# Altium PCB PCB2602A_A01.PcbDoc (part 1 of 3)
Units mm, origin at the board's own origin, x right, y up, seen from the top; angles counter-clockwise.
Board outline 30.4 x 45.4 mm, 8 copper layers (Top Layer, Signal Layer 2, Signal Layer 3, Signal Layer 4, Signal Layer 5, Signal Layer 6, Signal Layer 7, Bottom Layer), stack 1.594 mm thick; 180 components, 124 nets, 679 pads, 487 vias.
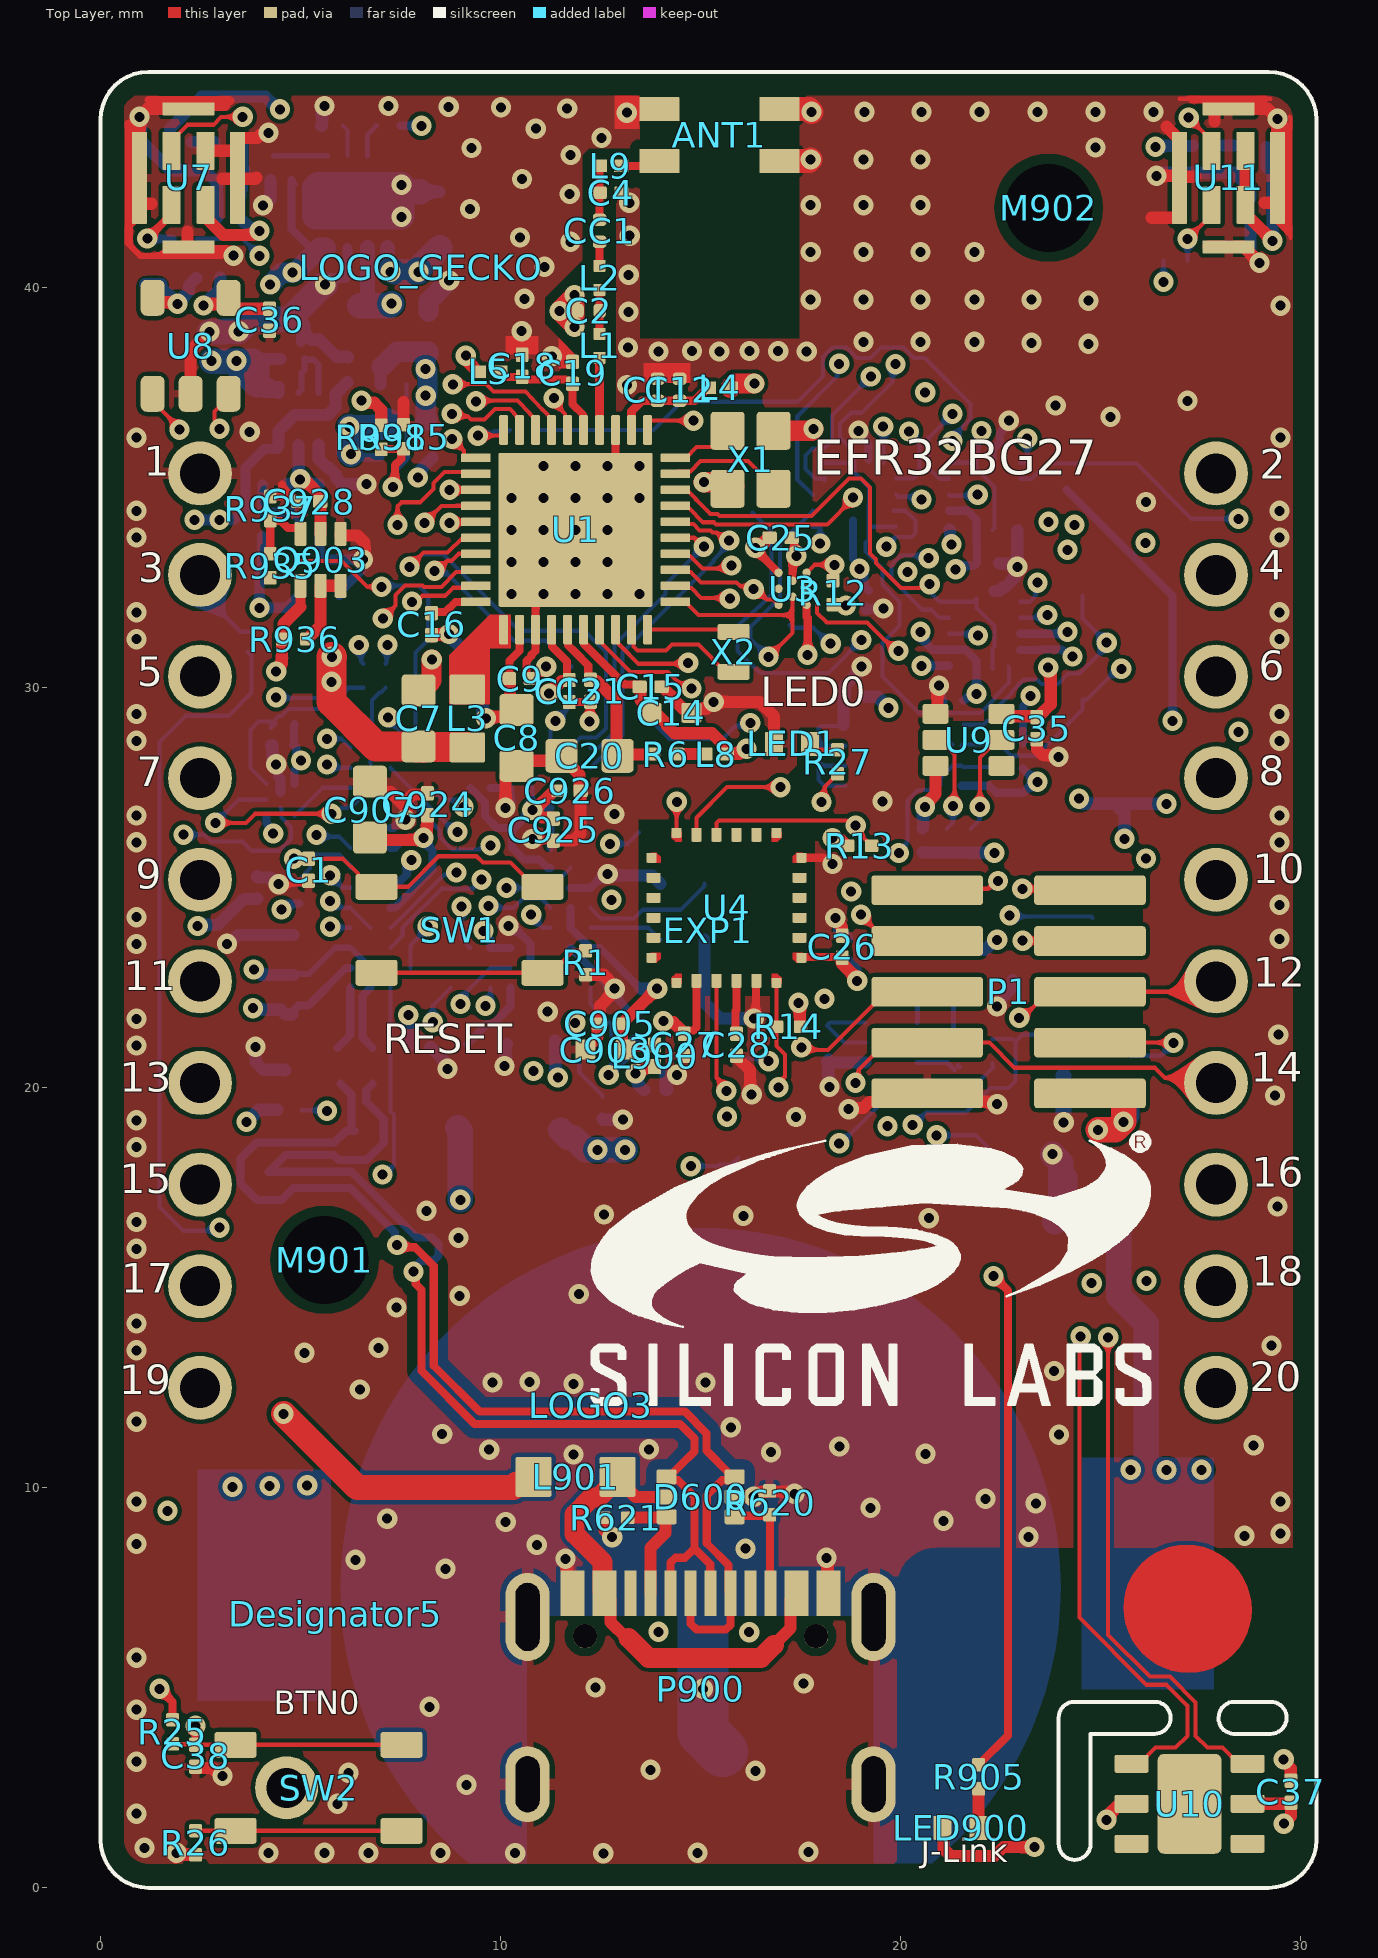
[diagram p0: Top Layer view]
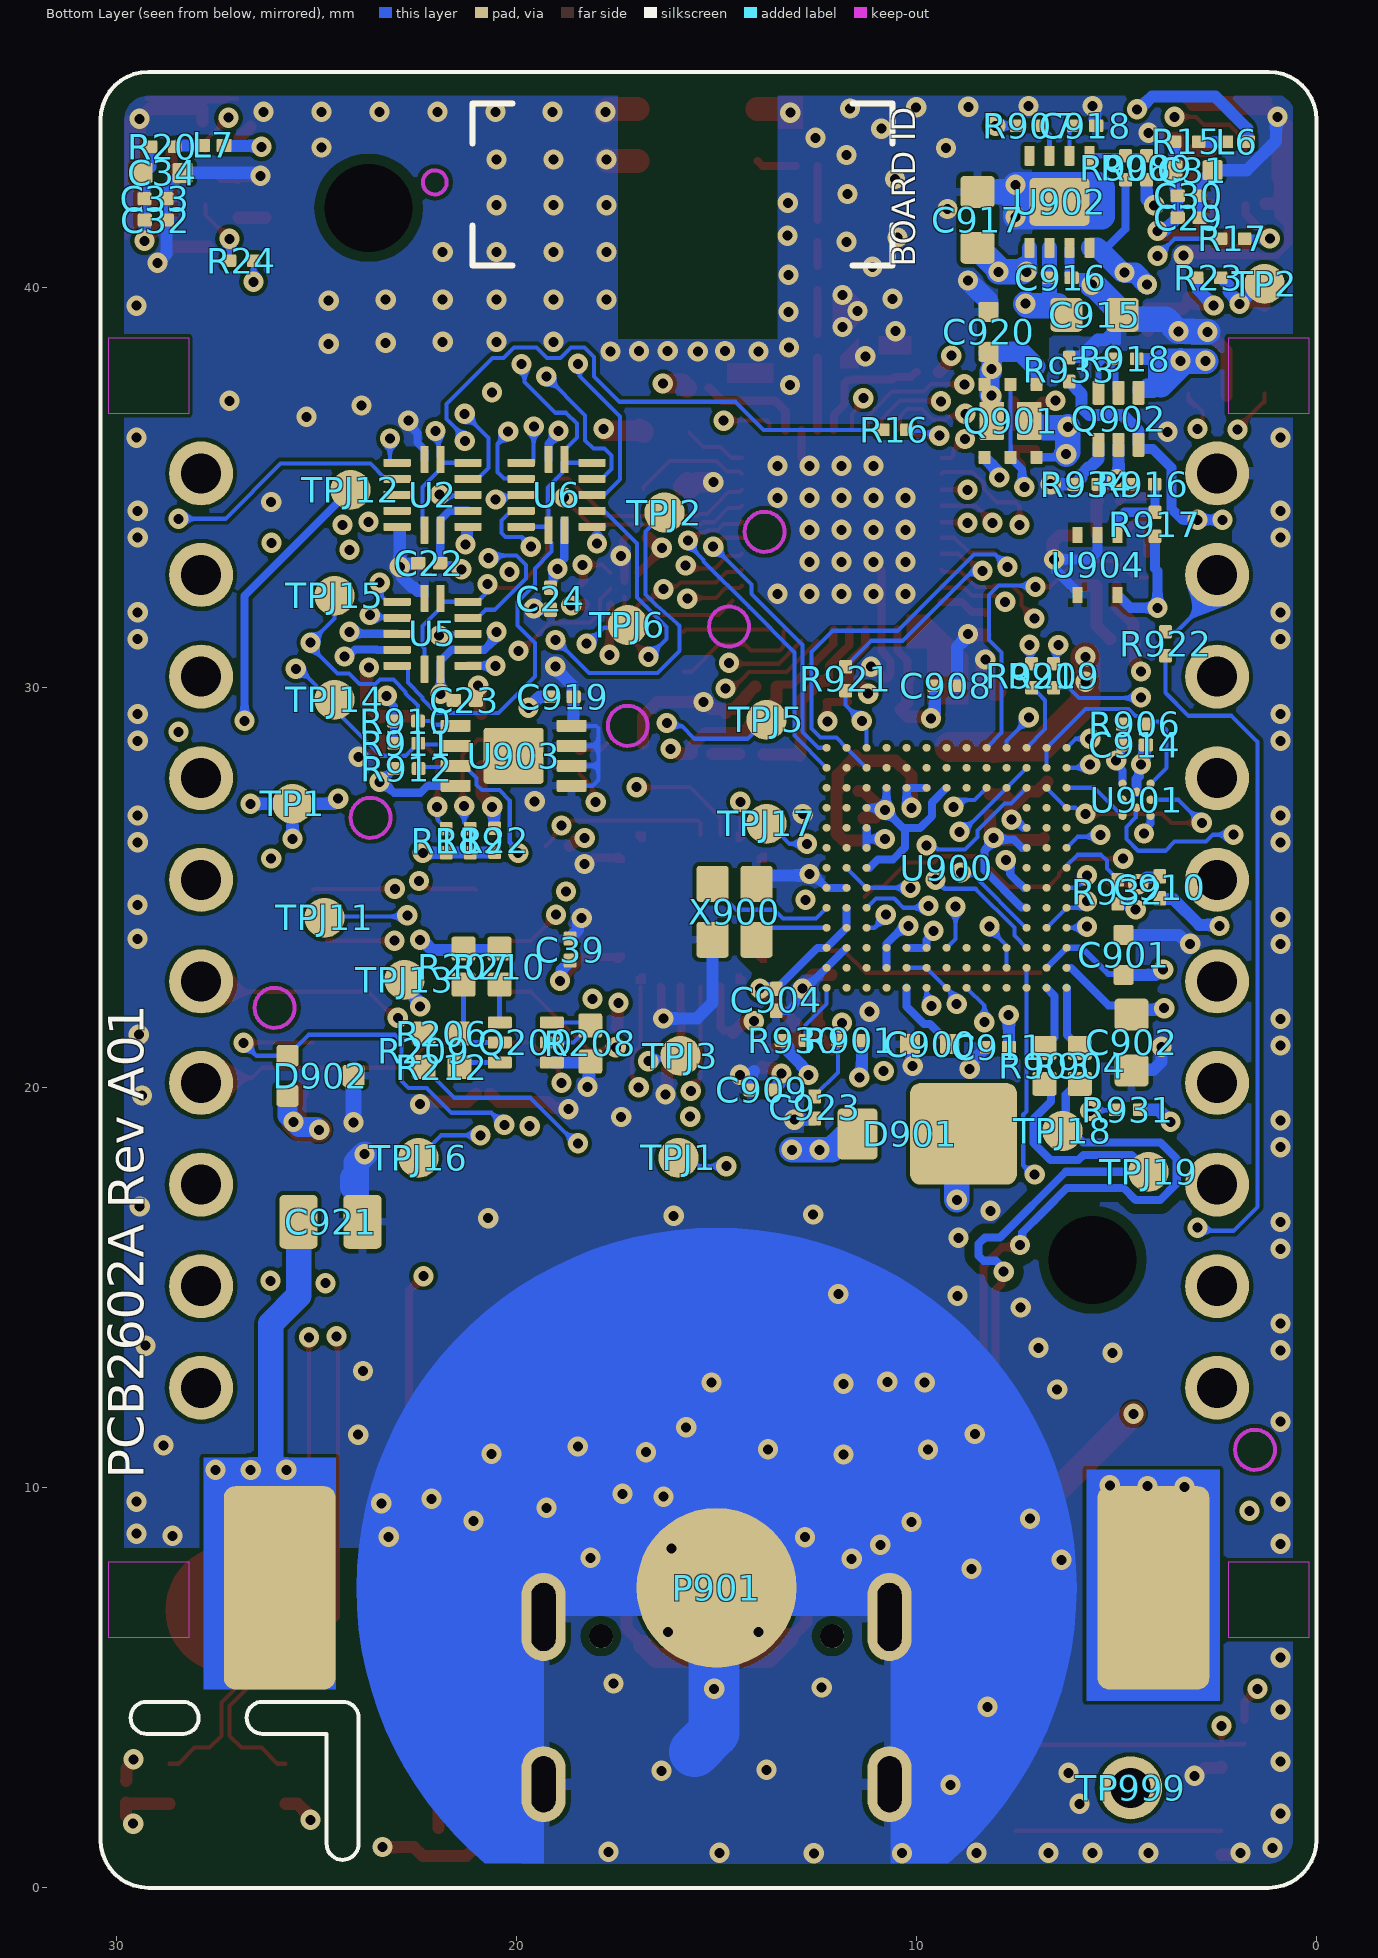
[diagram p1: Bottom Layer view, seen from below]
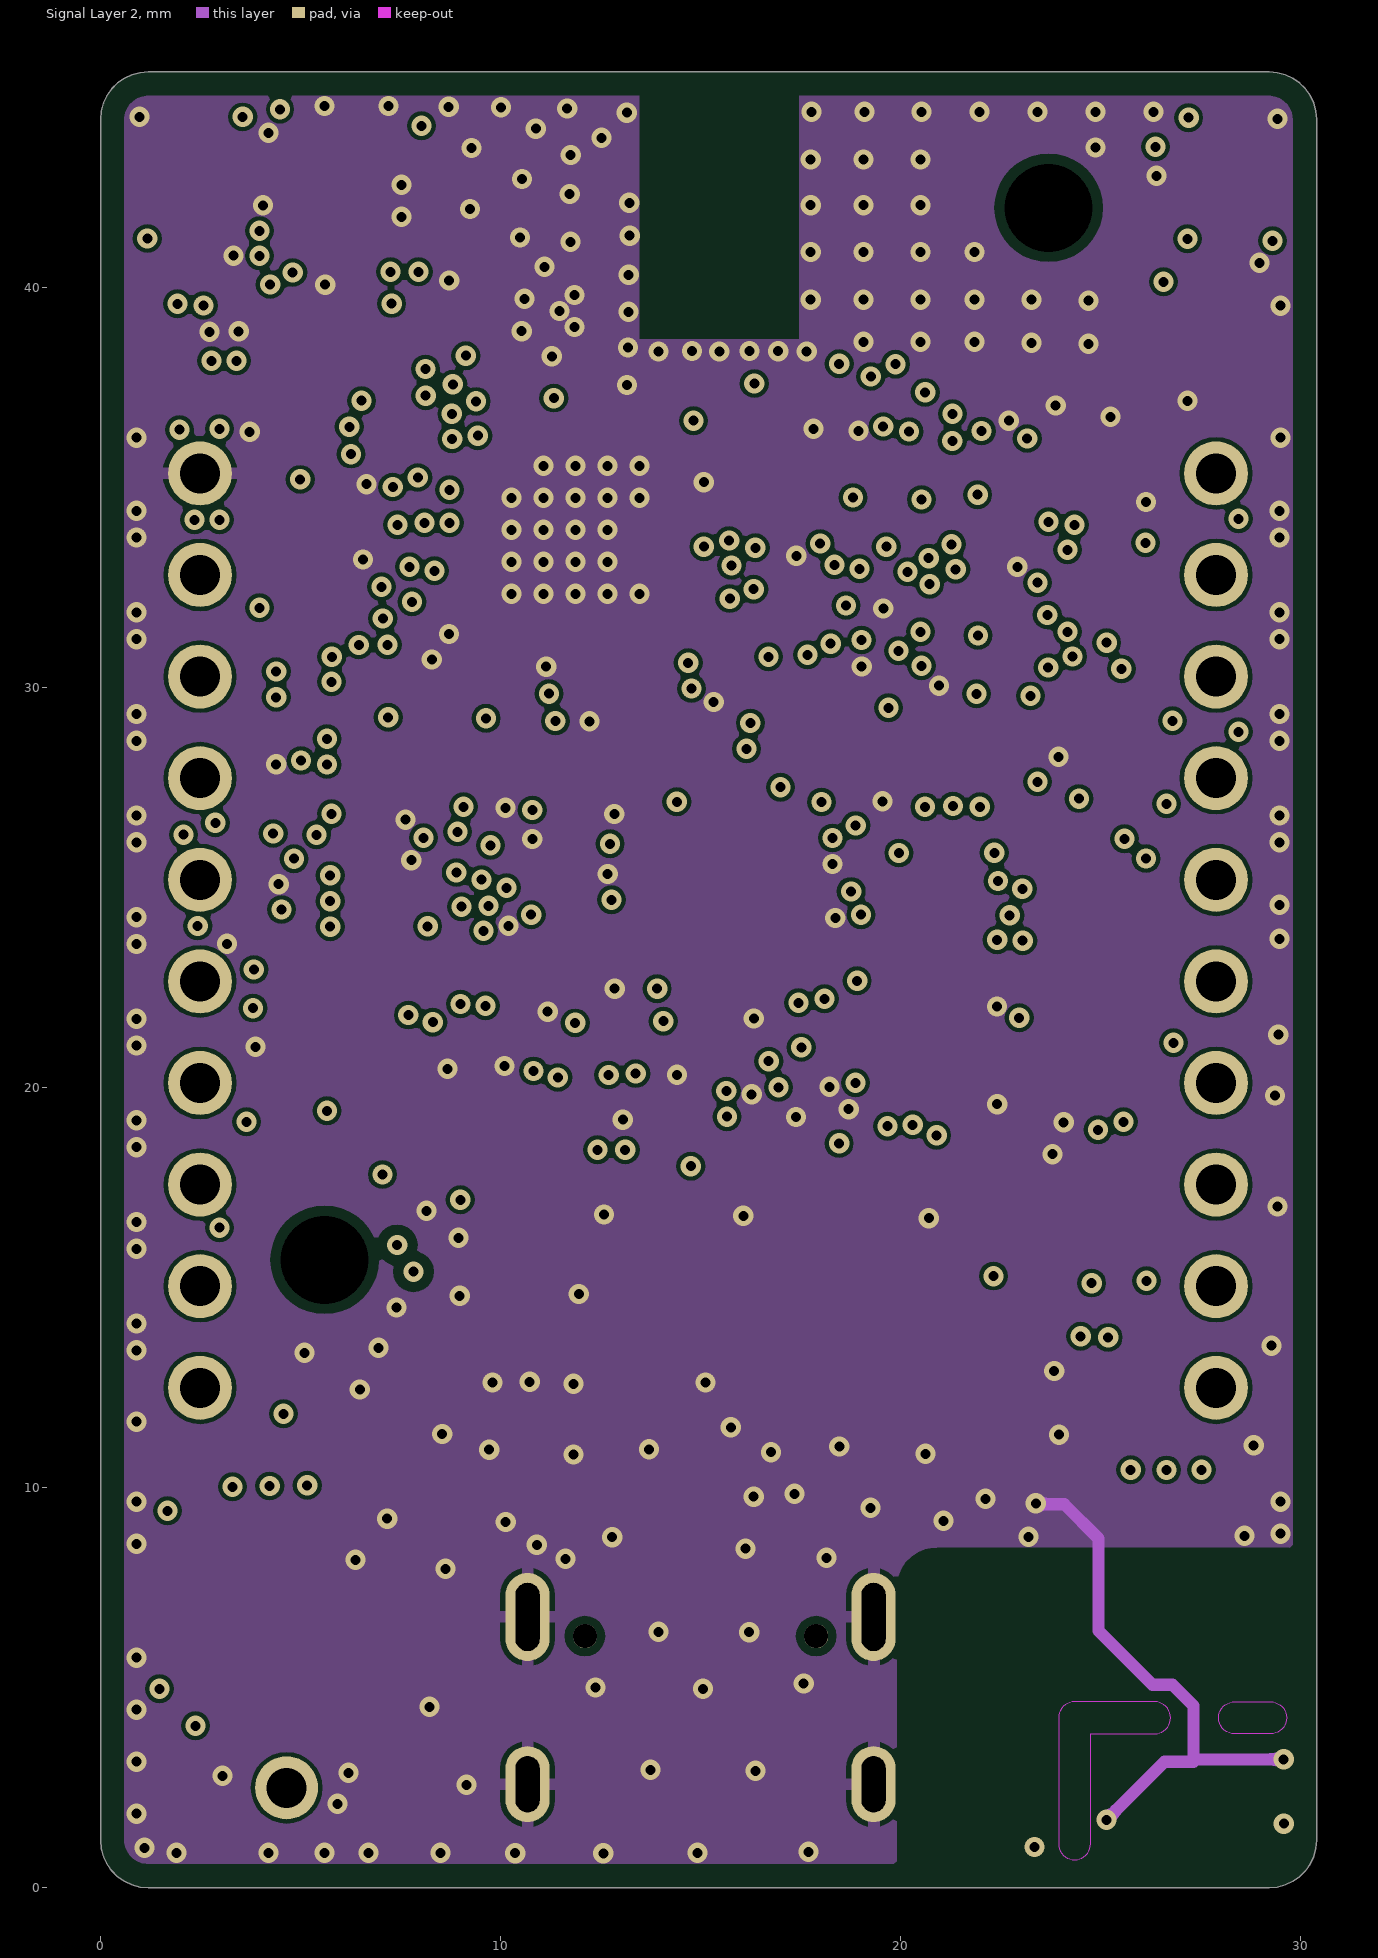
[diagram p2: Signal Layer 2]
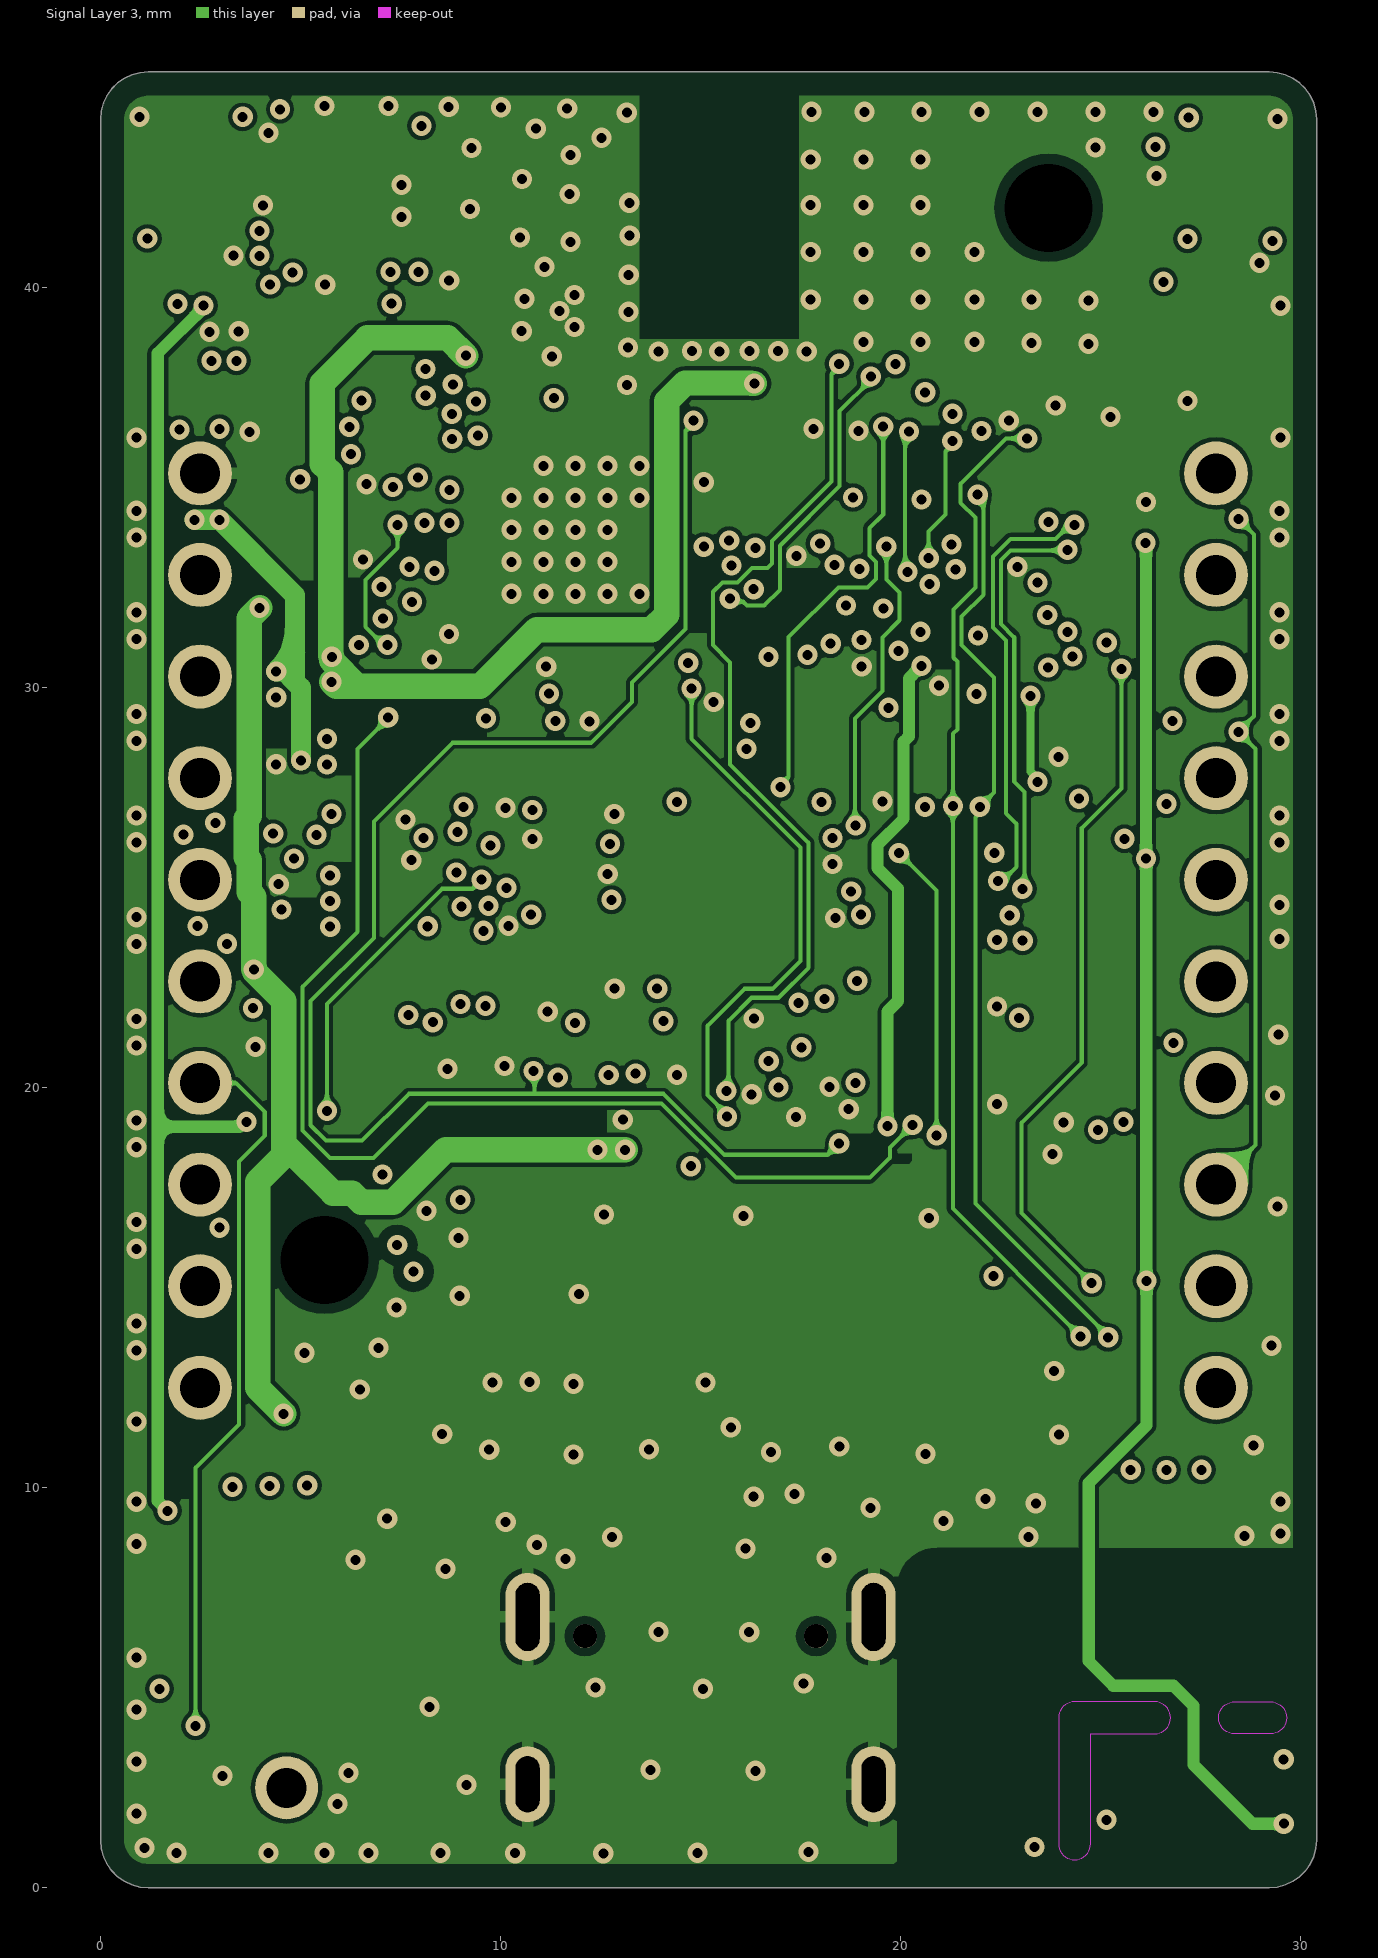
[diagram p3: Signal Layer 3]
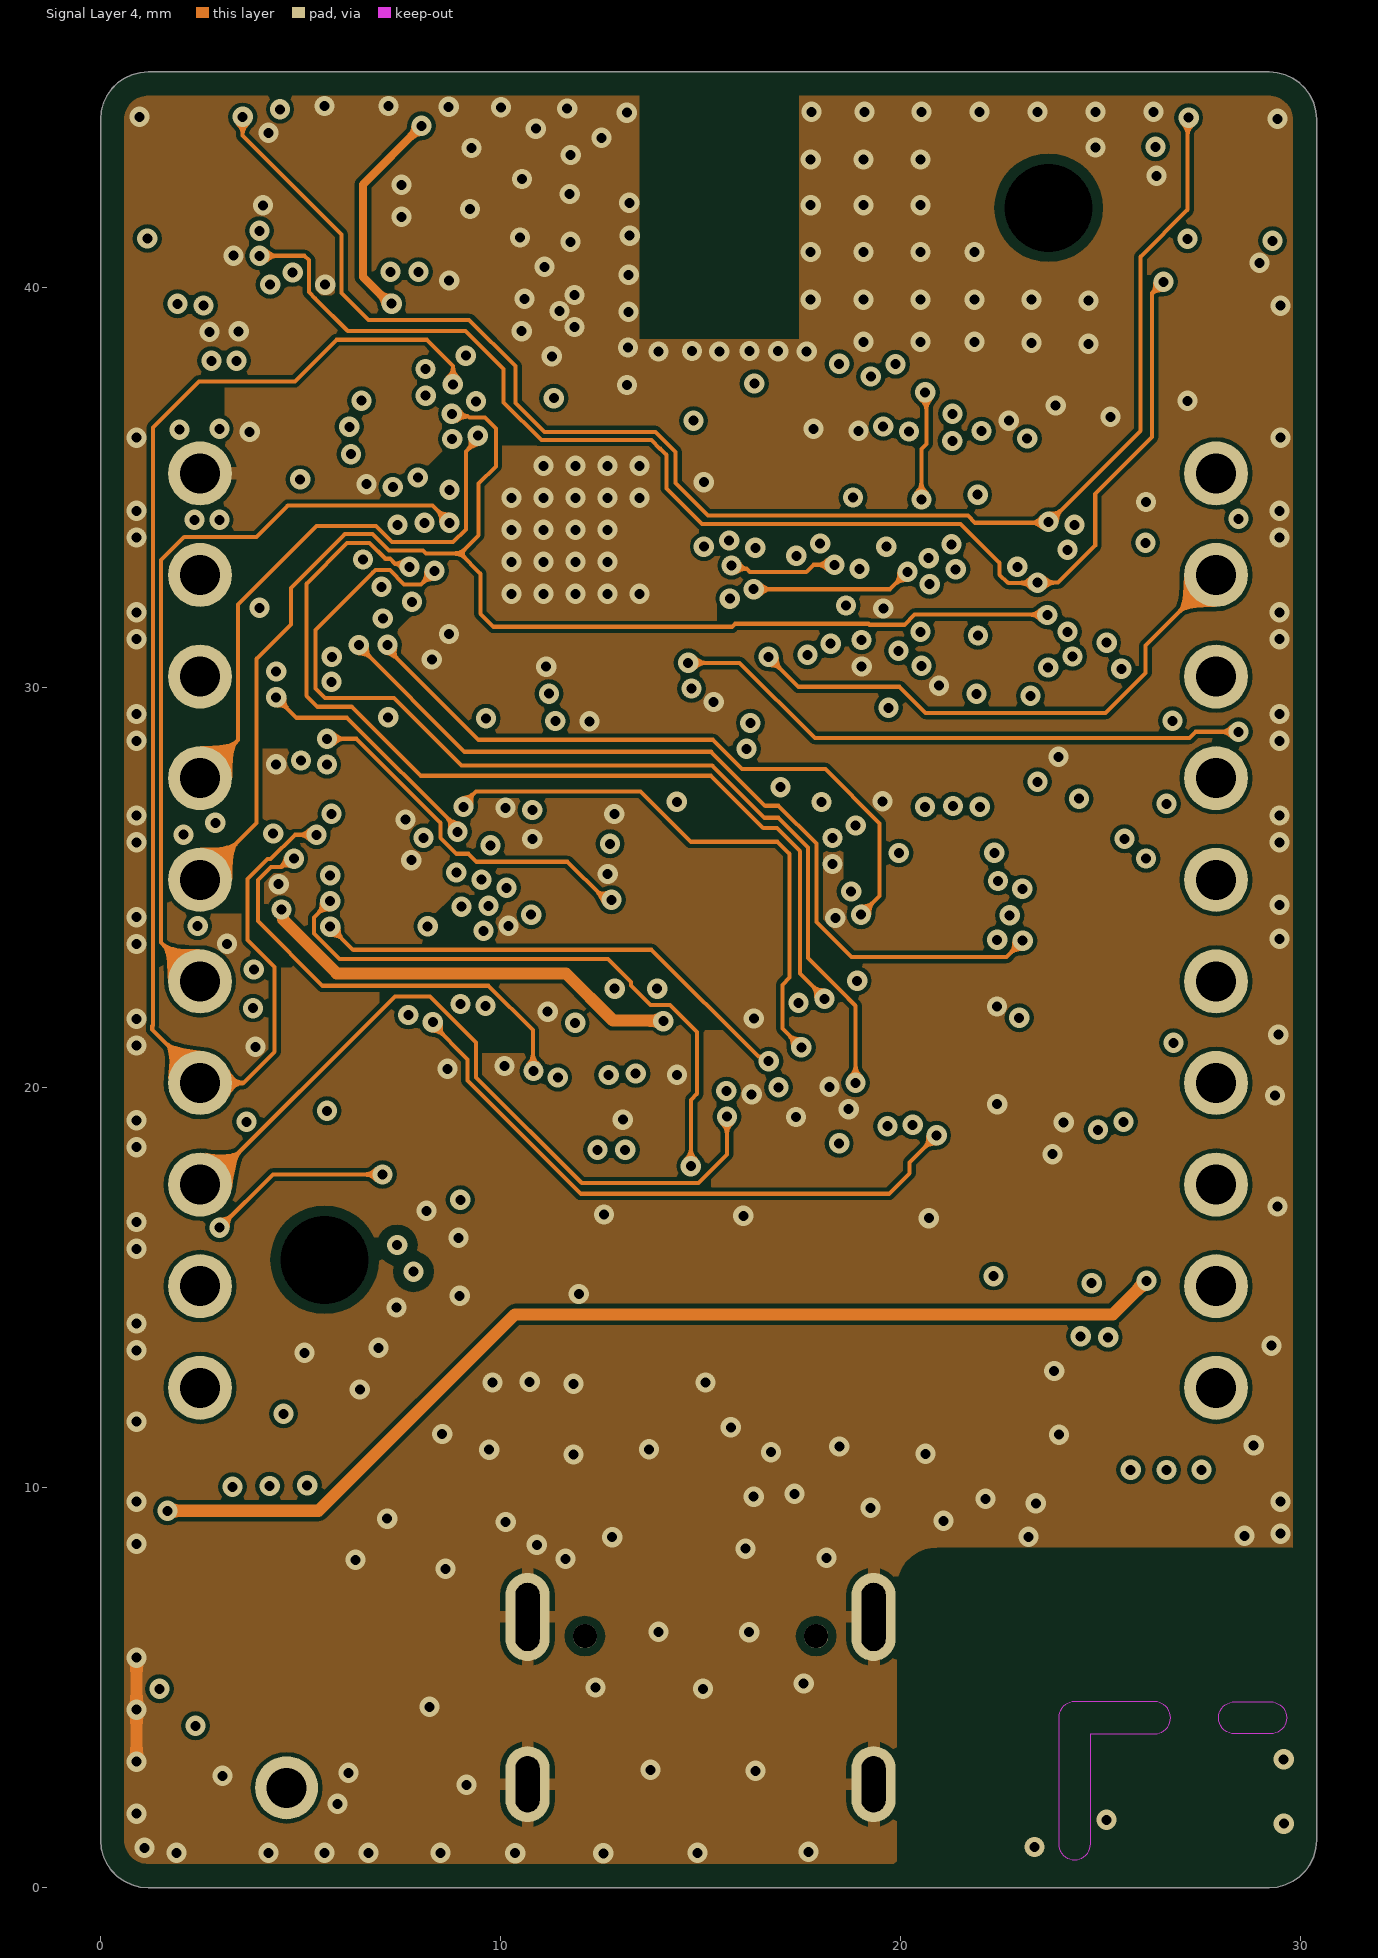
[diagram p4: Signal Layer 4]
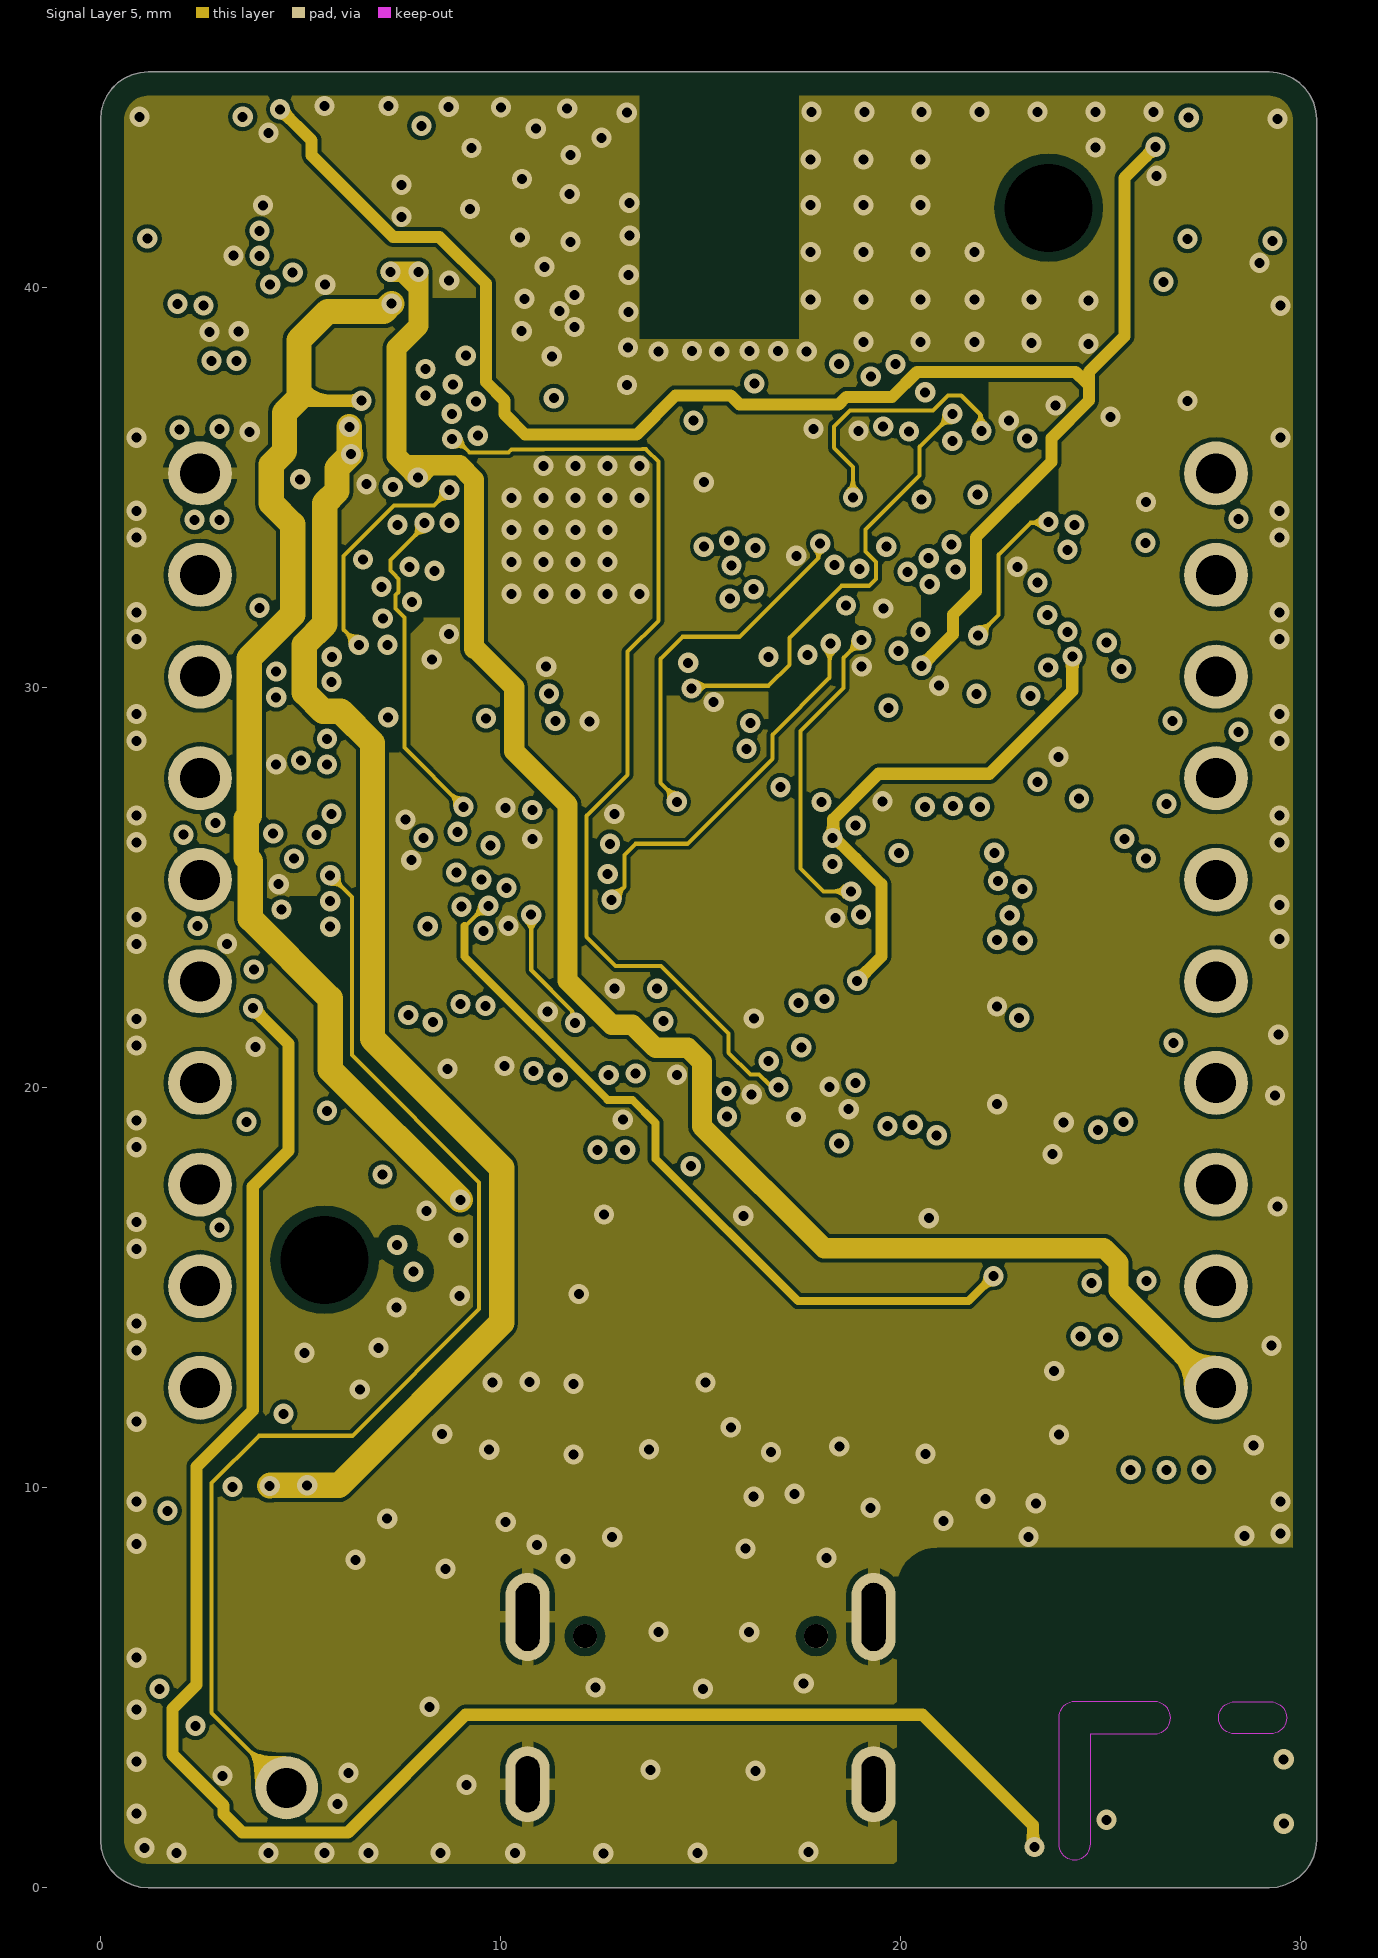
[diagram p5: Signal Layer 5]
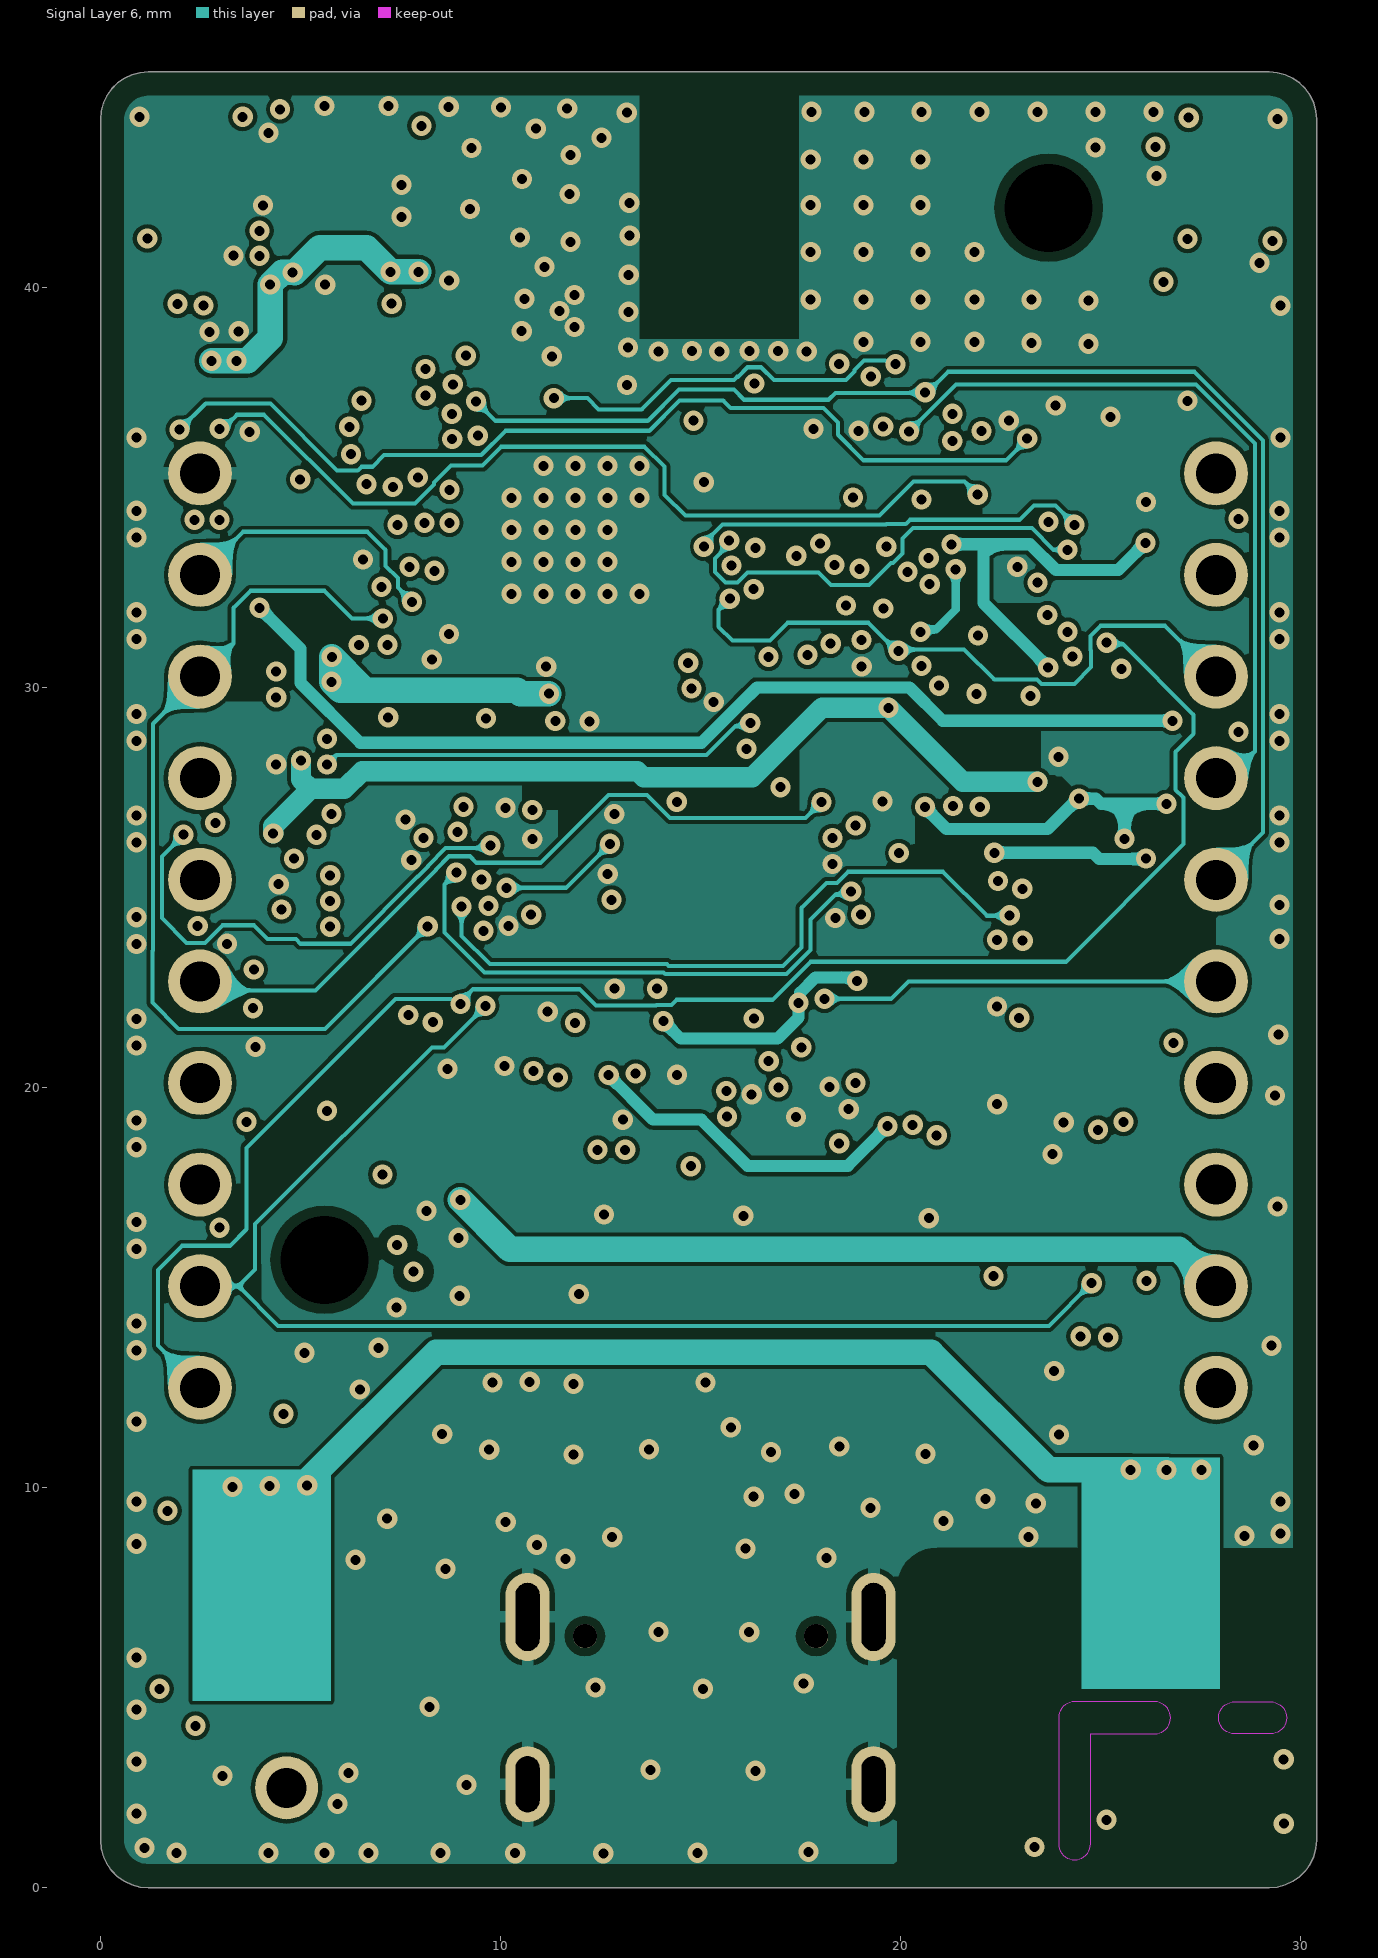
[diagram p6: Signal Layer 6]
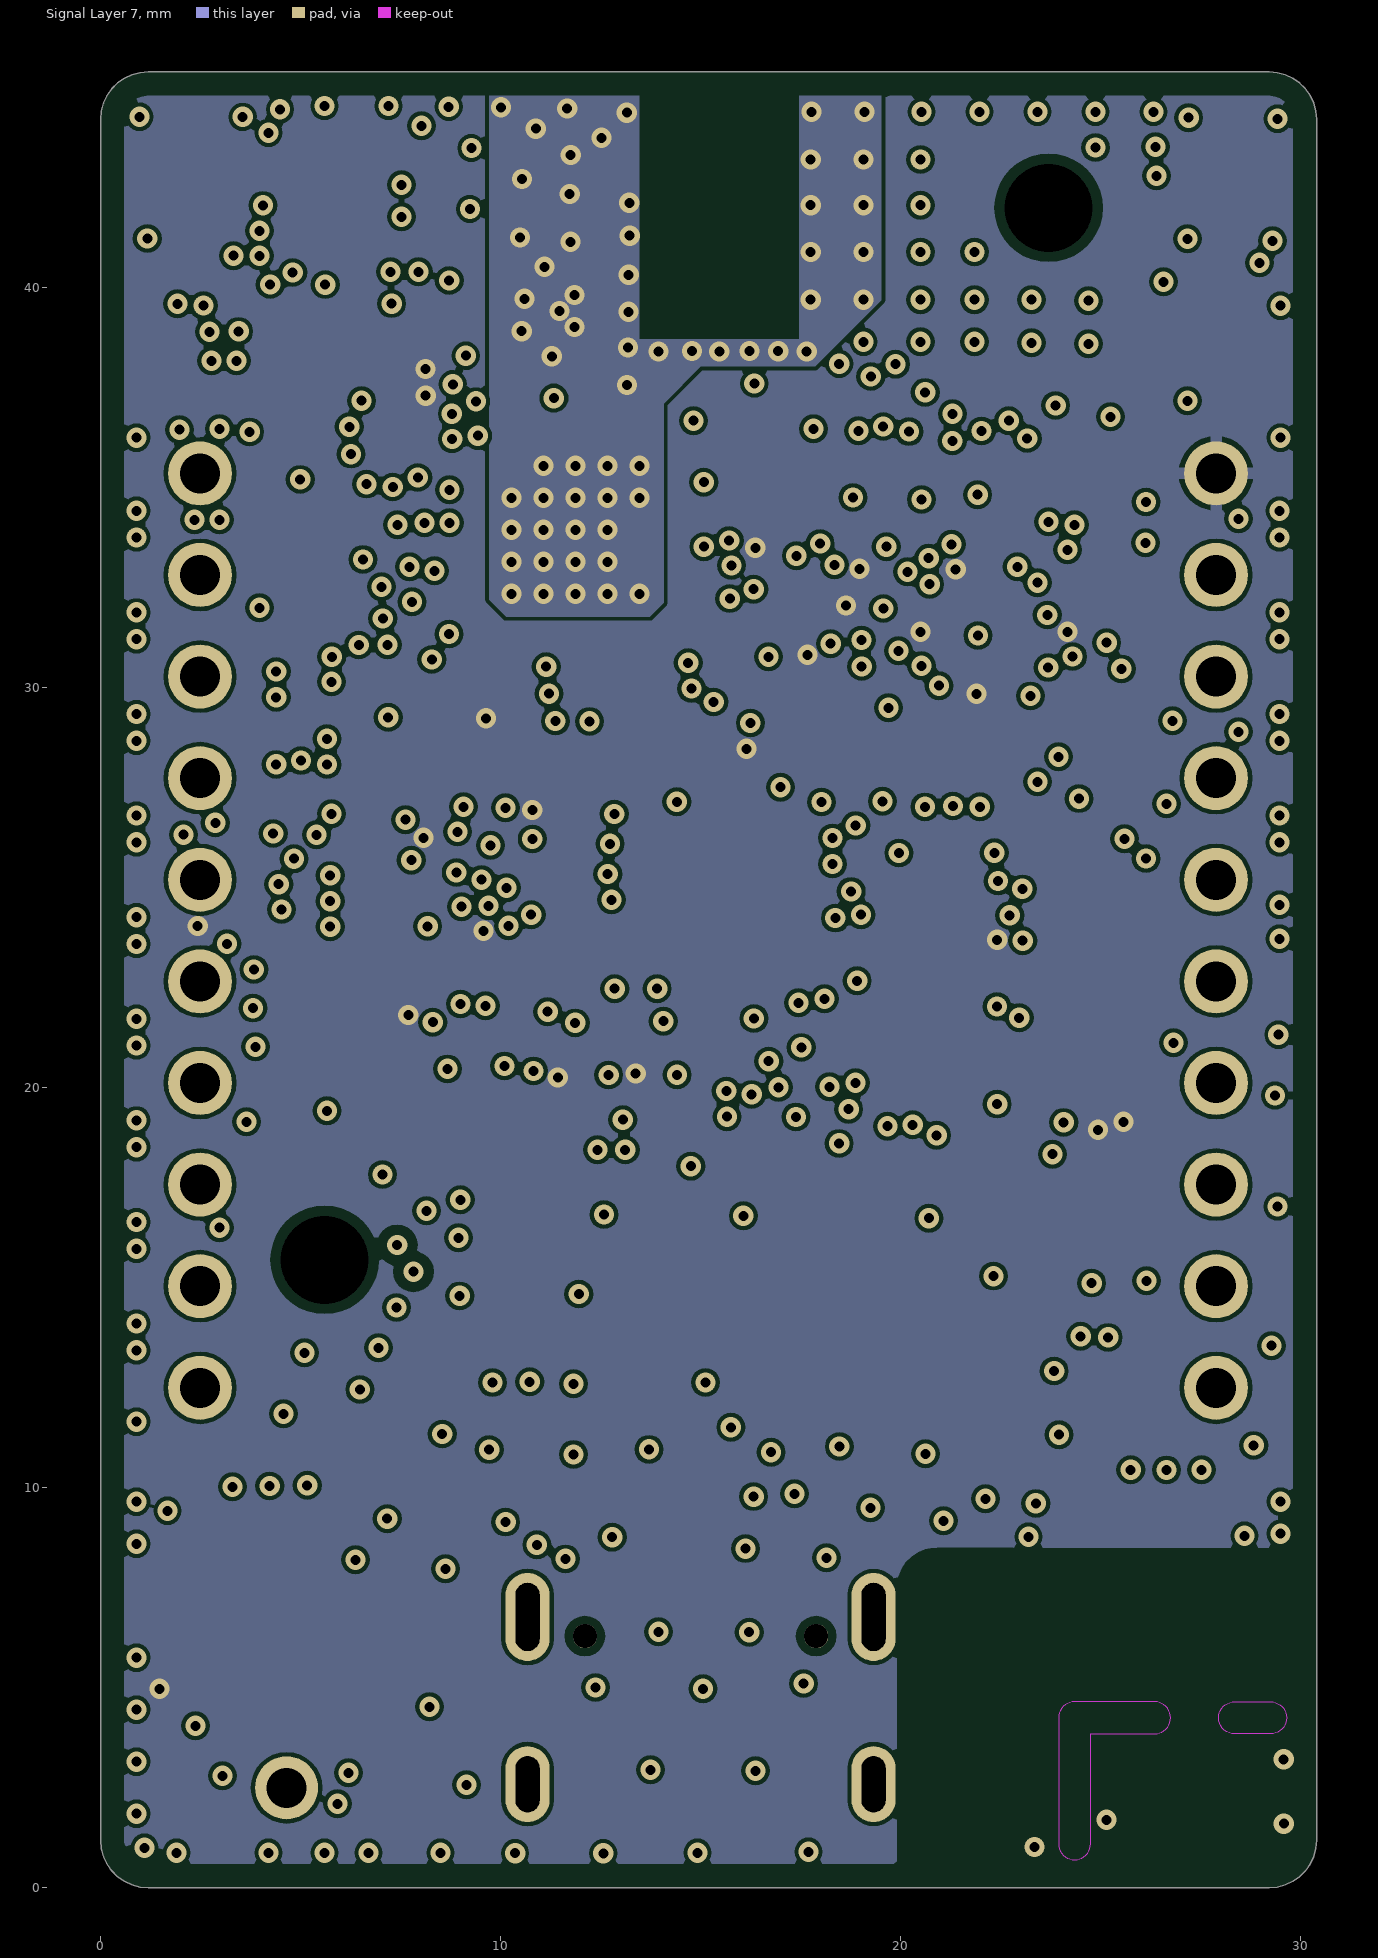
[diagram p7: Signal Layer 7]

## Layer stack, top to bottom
Top Solder: solder mask 0.05, Solder Resist, Dk 3.5
Top Layer: signal copper 0.038
Dielectric 1: prepreg 0.081, FR-4, Dk 4.2
Signal Layer 2: signal copper 0.018
Dielectric 2: core 0.203, FR-4, Dk 4.2
Signal Layer 3: signal copper 0.018
Dielectric 3: prepreg 0.24, FR-4, Dk 4.2
Signal Layer 4: signal copper 0.018
Dielectric 4: core 0.362, FR-4, Dk 4.2
Signal Layer 5: signal copper 0.018
Dielectric 5: prepreg 0.24, FR-4, Dk 4.2
Signal Layer 6: signal copper 0.018
Dielectric 6: core 0.203, FR-4, Dk 4.2
Signal Layer 7: signal copper 0.018
Dielectric  7: prepreg 0.081, FR-4, Dk 4.2
Bottom Layer: signal copper 0.038
Bottom Solder: solder mask 0.05, Solder Resist, Dk 3.5

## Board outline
0.279,0.424 0.16,0.594 0.074,0.782 0.02,0.983 0,1.189 0,44.21 0.02,44.416 0.074,44.616 0.16,44.804 0.279,44.974 0.427,45.122 0.597,45.241 0.785,45.328 0.985,45.381 1.191,45.399 29.211,45.399 29.417,45.381 29.618,45.328 29.806,45.241 29.976,45.122 30.123,44.974 30.242,44.804 30.329,44.616 30.382,44.416 30.4,44.21 30.4,1.189 30.382,0.983 30.329,0.782 30.242,0.594 30.123,0.424 29.976,0.277 29.806,0.16 29.618,0.071 29.417,0.018 29.211,0 1.191,0 0.985,0.018 0.785,0.071 0.597,0.16 0.427,0.277

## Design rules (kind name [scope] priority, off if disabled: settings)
AcuteAngle [All] p1: minimum=5.00000000000000E+0001 checktracksonly=FALSE
BoardOutlineClearance [All] p1: gap=0 ignorepadtopadclearanceinfootprint=FALSE except(0.2: THPad-OutlineEdge; 0.5: THPad-CavityEdge THPad-CutoutEdge THPad-SplitBarrior THPad-SplitContinuation Via-OutlineEdge Via-CavityEdge Via-CutoutEdge Via-SplitBarrior Via-SplitContinuation Fill-OutlineEdge Fill-CavityEdge Fill-CutoutEdge Fill-SplitBarrior Fill-SplitContinuation Poly-OutlineEdge Poly-CavityEdge Poly-CutoutEdge Poly-SplitBarrior Poly-SplitContinuation)
Clearance Clearance_RF [InNetClass('RF') vs InPolygon] p1: gap=0.25 ignorepadtopadclearanceinfootprint=FALSE
Clearance Clearance_USB [InNetClass('USB') vs InPolygon] p2: gap=0.25 ignorepadtopadclearanceinfootprint=FALSE
Clearance USB_LINE [InNet('DBGMCU_USB_DM') vs InNet('DBGMCU_USB_DP')] p3: gap=0.127 ignorepadtopadclearanceinfootprint=FALSE except(0: Arc-Hole Track-Hole SMDPad-Hole THPad-Hole Via-Hole Fill-Hole Poly-Hole Region-Hole Text-Hole)
Clearance Clearance_NPL [HasFootprint('HOLE_2.2_NPL')] p4: gap=0.25 ignorepadtopadclearanceinfootprint=FALSE
Clearance Clearance_NPL2 [(ObjectKind = 'Pad') And (Layer = 'MultiLayer') And (Net = 'No Net') And (PadIsPlated = 'False')] p5: gap=0.2 ignorepadtopadclearanceinfootprint=FALSE // P900 Clearance
Clearance Clearance_General [All] p6: gap=0.102 ignorepadtopadclearanceinfootprint=FALSE except(0: Arc-Hole Track-Hole SMDPad-Hole THPad-Hole Via-Hole Fill-Hole Poly-Hole Region-Hole Text-Hole)
ComponentClearance [All] p1: gap=0 collisioncheckmode=3 verticalgap=0 showdistances=FALSE
HoleToHoleClearance HoleToHoleClearance_ANT1toPAD [Incomponent ('ANT1') vs ISpad] p1: gap=0 allowstackedmicrovias=TRUE
HoleToHoleClearance HoleToHoleClearance_P5toSW4 [Incomponent ('P5') vs Incomponent ('SW4')] p2: gap=0 allowstackedmicrovias=TRUE
HoleToHoleClearance HoleToHoleClearance_R1toR2 [Incomponent ('R1') vs Incomponent ('R2')] p3: gap=0 allowstackedmicrovias=TRUE
HoleToHoleClearance HoleToHoleClearance_general [All] p4: gap=0.375 allowstackedmicrovias=TRUE
MinimumSolderMaskSliver [All] p1: minsoldermaskwidth=0.1
PolygonConnect PolygonConnect_PAD_DROWN [InPadClass('PAD_DROWN')] p1: connectstyle=Direct reliefconductorwidth=0.254 reliefentries=4 polygonreliefangle="90 Angle" airgapwidth=0.254
PolygonConnect PolygonConnect_general [All] p2: thpad.connectstyle=Relief thpad.reliefconductorwidth=0.3 thpad.reliefentries=4 thpad.polygonreliefangle="90 Angle" thpad.airgapwidth=0.127 smdpad.connectstyle=Relief smdpad.reliefconductorwidth=0.203 smdpad.reliefentries=4 smdpad.polygonreliefangle="90 Angle" smdpad.airgapwidth=0.102 via.connectstyle=Direct via.reliefconductorwidth=0.33 via.reliefentries=4 via.polygonreliefangle="90 Angle" via.airgapwidth=0.127
RoutingVias [All] p1: holewidth=0.25 width=0.508 viastyle="Through Hole" minholewidth=0.25 minwidth=0.508 maxholewidth=1 maxwidth=1.5 useviatemplates=TRUE viatemplateguid#1={6F1DD7E6-927C-44B2-B45B-632E0E9A9A8F} viatemplatename#1=v51h25m0mx0
ShortCircuit ShortCircuit_P5toSW4 [Incomponent ('P5') vs Incomponent ('SW4')] p1: allowed=TRUE
ShortCircuit ShortCircuit_ANTtoPAD [InNet('NetAT1_1') vs InNet('GND')] p2: allowed=TRUE
ShortCircuit ShortCircuit_General [All] p3: allowed=FALSE
SilkToSilkClearance [All] p1: silktosilkclearance=0.102
SilkToSolderMaskClearance [IsPad] p1: minsilkscreentomaskgap=0.102 clearancetoexposedcopper=TRUE
SolderMaskExpansion [All] p1: expansion=0.05 istentingtop=FALSE
UnRoutedNet [All] p1: checkbadconnections=TRUE
Width [All] p1: maxlimit=5.08 minlimit=0.1 preferedwidth=0.1
23 further rules are at their usual default settings.

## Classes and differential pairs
net class RF: N16820078 N16820097 N16820130 N17051201 N17433295
net class USB: CTRL_MCU_PF10 CTRL_MCU_PF11 CTRL_MCU_USB_DM CTRL_MCU_USB_DP
pad class P5_2: P5-2

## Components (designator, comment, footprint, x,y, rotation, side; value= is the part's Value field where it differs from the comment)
ANT1 "2450AT18D0100" ANT_JOH_2450AT18D0100 15.472,43.816 r0 top
C1 "100N" C0201 5.2,25.45 r270 top
C2 "1P6" C0201_L 12.2,39.425 r180 top
C4 "1P5" C0201 12.75,42.375 r0 top
C7 "4U7" C0603 7.95,29.235 r90 top
C8 "10U" C0603 10.4,28.75 r270 top
C9 "100N" C0201 10.483,30.23 r0 top
C11 "100N" C0201_L 13.925,37.45 r90 top
C12 "120P" C0201_L 14.475,37.45 r90 top
C13 "100N" C0201 11.719,29.918 r270 top
C14 "1U" C0402 14.27,29.375 r0 top
C15 "100N" C0201 13.75,30.025 r0 top
C16 "2U2" C0201 8.274,31.592 r270 top
C18 "100N" C0201 10.54,38.05 r90 top
C19 "120P" C0201 11.8,37.872 r90 top
C20 "10U" C0603 12.225,28.3 r180 top
C21 "10N" C0201 12.25,29.925 r270 top
C22 "100N" C0201 22.184,33.115 r0 bottom
C23 "100N" C0201 21.292,29.685 r180 bottom
C24 "100N" C0201 19.15,32.225 r270 bottom
C25 "100N" C0201 17,33.75 r0 top
C26 "100N" C0201 18.544,23.528 r90 top
C27 "10N" C0201 14.592,21.075 r270 top
C28 "470N" C0201 15.9,21.075 r270 top
C29 "150p" C0201 3.2,41.75 r180 bottom
C30 "100N" C0201 3.196,42.3 r180 bottom
C31 "1U" C0402 3.099,42.939 r180 bottom
C32 "150p" C0201 29.02,41.692 r180 bottom
C33 "100N" C0201 29.027,42.228 r180 bottom
C34 "1U" C0402 28.85,42.875 r180 bottom
C35 "100N" C0201 23.404,28.989 r270 top
C36 "100N" C0201 4.225,39.2 r270 top
C37 "100N" C0201 29.761,2.401 r90 top
C38 "1N" C0201 2.375,3.3 r270 top
C39 "2U2" C0201 18.662,23.456 r90 bottom
C900 "1U" C0402 9.66,21.089 r0 bottom
C901 "1U" C0402 4.824,23.322 r90 bottom
C902 "4U7" C0603 4.625,21.133 r270 bottom
C903 "1U" C0402 12.619,20.956 r180 top
C904 "10N" C0201 13.506,22.196 r270 bottom
C905 "10N" C0201 12.733,21.6 r180 top
C907 "4U7" C0603 6.735,26.953 r90 top
C908 "100N" C0201 9.267,30.048 r180 bottom
C909 "100N" C0201 13.873,19.947 r0 bottom
C910 "100N" C0201 3.919,25.011 r90 bottom
C911 "100N" C0201 7.964,21.014 r0 bottom
C914 "100N" C0201 4.542,28.571 r180 bottom
C915 "4U7" C0603 5.55,39.325 r180 bottom
C916 "100N" C0201 6.4,40.25 r180 bottom
C917 "10U" C0603 8.475,41.7 r90 bottom
C918 "33N" C0201 5.784,44.05 r180 bottom
C919 "100N" C0201 18.85,29.775 r180 bottom
C920 "1U" C0402 8.2,38.9 r90 bottom
C921 "47U" C0805 24.65,16.65 r180 bottom
C923 "100N" C0201 12.548,19.507 r270 bottom
C924 "100N" C0201 8.174,27.088 r90 top
C925 "100N" C0201 11.321,26.454 r270 top
C926 "100N" C0201 11.725,27.425 r0 top
C928 "100N" C0201 5.218,34.656 r180 top
CC1 "18P" C0201_L 12.475,41.425 r90 top
D600 "DT1446-04" SOT563_DIODES 15,9.775 r180 top
D901 "SS3P3" DO220AA 9.677,18.847 r0 bottom
D902 "ESD" SOT663_NXP 24.9,20.3 r180 bottom
Designator5 "Comment" LOGO_SEGGER_8.0X4.0_SM 5.875,6.85 r0 top
EXP1 "HEADER_2X10_2.54MM_TH_SPLIT" HDR_M254-1X10_PLUS_1X10_NO_3D 27.886,35.36 r270 top
L1 "2N0" COIL_0201_L 12.475,38.55 r90 top
L2 "3N2" COIL_0201_L 12.475,40.25 r90 top
L3 "2U2" COIL_0603_L 9.169,29.235 r270 top
L4 "742692004" COIL_0201 15.475,37.5 r180 top
L5 "742692004" COIL_0201 9.722,37.9 r0 top
L6 "742692004" COIL_0201 2,43.65 r0 bottom
L7 "742692004" COIL_0201 27.583,43.558 r0 bottom
L8 "742692004" COIL_0201 15.38,28.343 r180 top
L9 "1N5" COIL_0201 12.745,43.05 r0 top
L900 "742692004" COIL_0201 13.85,20.8 r90 top
L901 "782853231" COIL_0805_H0.9 11.875,10.275 r180 top
LED1 "YELLOW" LED_0402_CAT2 17.291,28.6 r180 top
LED900 "BLUE" LED_0402_CAT2 21.5,1.5 r0 top
LOGO3 "Comment" LOGO_SILABS_W14.0_SILK 12.25,12.065 r0 top
LOGO_GECKO "Comment" LOGO_GECKO_H4.0_SM 8.008,40.516 r0 top
M901 "2.2 MM" HOLE_2.2_NPL 5.6,15.7 r0 top
M902 "2.2 MM" HOLE_2.2_NPL 23.7,42 r0 top
P1 "MINI-SIMPLICITY" FTSH_105_01_L_DV_K 22.7,22.4 r90 top
P900 "BEC_80259-1021" BEC_80259-1021 15,0.5 r0 top
P901 "CR2032" BAT_HOLD_MPD_BK-912_CR2032 15,7.5 r180 bottom
Q200 "DMC2400UV" SOT563 19.766,21.133 r0 bottom
Q901 "SiA527DJ" POWERPAK_SC70-6 7.65,36.675 r90 bottom
Q902 "DMC2400UV" SOT563 4.95,36.725 r90 bottom
Q903 "DMC2400UV" SOT563 5.5,33.2 r270 top
R1 "100R" R0201 12.125,23.125 r90 top
R6 "1R" R0201 14.129,28.341 r180 top
R12 "330K" R0201 18.312,32.38 r90 top
R13 "100K" R0201 18.975,26.05 r0 top
R14 "100K" R0201 17.2,21.525 r180 top
R15 "10R" R0201 3.25,43.65 r180 bottom
R16 "22R" R0201 10.541,36.449 r180 bottom
R17 "22R" R0201 2.1,41.225 r0 bottom
R18 "4K7" R0201 21.758,26.175 r90 bottom
R19 "4K7" R0201 21.158,26.175 r90 bottom
R20 "10R" R0201 28.85,43.525 r180 bottom
R22 "100K" R0201 20.549,26.187 r90 bottom
R23 "100K" R0201 2.7,40.25 r180 bottom
R24 "22R" R0201 26.875,40.675 r180 bottom
R25 "1M" R0201 1.8,3.9 r270 top
R26 "100R" R0201 2.375,1.125 r270 top
R27 "2K7" R0201 18.425,28.15 r90 top
R206 "100R" R0402 21.871,21.351 r180 bottom
R207 "10K" R0402 21.325,23.03 r90 bottom
R208 "10K" R0402 18.158,21.107 r90 bottom
R209 "0R" R0201 22.321,20.921 r90 bottom
R210 "0R" R0402 20.427,23.027 r90 bottom
R212 "100R" R0402 21.871,20.514 r0 bottom
R620 "5K1" R0201 16.725,9.625 r270 top
R621 "5K1" R0201 12.875,9.25 r0 top
R901 "1K" R0201 11.668,21.182 r180 bottom
R903 "33R" R0402 6.8,20.55 r90 bottom
R904 "33R" R0402 5.92,20.55 r90 bottom
R905 "5K76" R0201 21.95,2.775 r270 top
R906 "10K" R0201 4.548,29.091 r0 bottom
R907 "10K" R0201 7.2,44.05 r0 bottom
R908 "180K" R0201 4.775,43 r270 bottom
R909 "110K" R0201 4.25,43 r90 bottom
R910 "4K7" R0201 22.765,29.167 r0 bottom
R911 "4K7" R0201 22.757,28.612 r0 bottom
R912 "10K" R0201 22.751,27.979 r0 bottom
R915 "4K7" R0201 7.575,36.275 r270 top
R916 "4K7" R0201 4.349,35.087 r180 bottom
R917 "10K" R0201 4.04,34.087 r90 bottom
R918 "33K" R0201 4.8,38.225 r180 bottom
R919 "470R" R0201 6.575,30.3 r90 bottom
R920 "470R" R0201 7.125,30.3 r90 bottom
R921 "470R" R0201 11.775,30.225 r90 bottom
R922 "470R" R0201 3.776,31.101 r90 bottom
R930 "1K" R0201 13.075,21.185 r0 bottom
R931 "1K" R0201 4.725,19.45 r180 bottom
R932 "1K" R0201 4.97,24.901 r270 bottom
R933 "100K" R0201 6.183,37.956 r90 bottom
R934 "4K7" R0201 5.761,35.085 r0 bottom
R935 "1K" R0201 4.242,33.052 r90 top
R936 "33K" R0201 4.855,31.218 r180 top
R937 "100K" R0201 4.244,34.481 r90 top
R938 "100R" R0201 7.019,36.262 r90 top
SW1 "PTS810" SW_CK_PTS810_SJM_250 8.975,23.95 r0 top
SW2 "PTS810" SW_CK_PTS810_SJM_250 5.45,2.5 r0 top
TP1 "TPJ_SMD" TP_1.0_SMD 25.6,27.1 r180 bottom
TP2 "TPJ_SMD" TP_1.0_SMD 1.3,40.1 r180 bottom
TP999 "PROTO_TH" PROTO_TH 4.65,2.5 r180 bottom
TPJ1 "TPJ_SMD" TP_1.0_SMD 15.95,18.25 r90 bottom
TPJ2 "TPJ_SMD" TP_1.0_SMD 16.3,34.38 r90 bottom
TPJ3 "TPJ_SMD" TP_1.0_SMD 15.9,20.8 r90 bottom
TPJ5 "TPJ_SMD" TP_1.0_SMD 13.75,29.2 r90 bottom
TPJ6 "TPJ_SMD" TP_1.0_SMD 17.22,31.57 r90 bottom
TPJ11 "TPJ_SMD" TP_1.0_SMD 24.8,24.25 r90 bottom
TPJ12 "TPJ_SMD" TP_1.0_SMD 24.15,34.95 r90 bottom
TPJ13 "TPJ_SMD" TP_1.0_SMD 22.8,22.7 r90 bottom
TPJ14 "TPJ_SMD" TP_1.0_SMD 24.55,29.7 r90 bottom
TPJ15 "TPJ_SMD" TP_1.0_SMD 24.55,32.3 r90 bottom
TPJ16 "TPJ_SMD" TP_1.0_SMD 22.45,18.25 r90 bottom
TPJ17 "TPJ_SMD" TP_1.0_SMD 13.75,26.6 r90 bottom
TPJ18 "TPJ_SMD" TP_1.0_SMD 6.35,18.92 r90 bottom
TPJ19 "TPJ_SMD" TP_1.0_SMD 4.2,17.9 r90 bottom
U1 "EFR32BG27" QFN40_M040_5.0X5.0_EP_SL 11.875,33.95 r180 top
U2 "TS3A4751" QFN14_M040_2.0X2.0_TI_RUC 22.1,34.825 r0 bottom
U3 "MX25R8035F" BGA8_M040_1.24X1.75_WLCSP 17.3,32.475 r0 top
U4 "ICM-20689" QFN24_M050_4.0X4.0_NO_EP_ICM-20689 15.65,24.5 r0 top
U5 "TS3A4751" QFN14_M040_2.0X2.0_TI_RUC 22.1,31.35 r0 bottom
U6 "TS3A4751" QFN14_M040_2.0X2.0_TI_RUC 19,34.825 r0 bottom
U7 "SPK0641HT4H-1" MIC_KNOWLES_SPK0641HT4H-1 2.2,42.75 r0 top
U8 "Si7210" SOT23-5 2.25,38.55 r90 top
U9 "VEML6035" SENS_VISH_VEML6035 21.7,28.7 r0 top
U10 "Si7021" DFN6_M100_3.0X3.0_EP_SI7021 27.225,2.1 r0 top
U11 "SPK0641HT4H-1" MIC_KNOWLES_SPK0641HT4H-1 28.2,42.75 r0 top
U900 "EFM32GG12B410F1024GL120-A" BGA120_M050_7.0X7.0_EFM32GGR 9.25,25.5 r270 bottom
U901 "MX25R8035F" BGA8_M040_1.24X1.75_WLCSP 4.5,27.2 r180 bottom
U902 "LP3982ILD-ADJ" LLP8_MA65_W3.0 6.425,42.15 r90 bottom
U903 "24AA024" TDFN8_M050_2.0X3.0_EP 20.075,28.3 r0 bottom
U904 "BD4842FVE" SOTFL50P160X60-5L 5.475,33.075 r270 bottom
X1 "38.4 MHz" X_TAI-SAW_TZ3398B-4 16.25,35.7 r270 top
X2 "32.768 kHz" X_KDS_DST1610A_1610 15.828,30.9 r270 top
X900 "48 MHz" X_KDS_DSX211SH_2.0X1.65-4 14.55,24.4 r90 bottom

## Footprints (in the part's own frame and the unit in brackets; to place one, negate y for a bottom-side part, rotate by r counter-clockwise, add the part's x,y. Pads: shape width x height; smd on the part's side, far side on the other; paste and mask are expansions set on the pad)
ANT_JOH_2450AT18D0100 [mm] "Antenna, Johanson 2450AT18D0100"
  rrect5% 1x0.6 smd: 1(-1.5,-0.65) 2(1.5,-0.65) 3(1.5,0.65) 4(-1.5,0.65)
  body extent -1.6,-0.8 1.6,0.8, height 1.41
BAT_HOLD_MPD_BK-912_CR2032 [mil] "MPD Battery Holder BK-912 (for CR2032)"
  rrect20% 110x200 smd: 1(-430,0) 1(430,0)
  round 157.48 smd paste-295.67 mask-82.68: 2(0,0)
  body extent -450,-394 450,394, height 171
BEC_80259-1021 [mm] "USB Type C Connector 16 Circuits"
  round 0.6 hole 0.6 unplated mask+0: 1(-2.89,5.79) 2(2.89,5.79)
  rect 0.6x1.14 smd mask+0.05: A1_B12(-3.2,6.86) A4_B9(-2.4,6.86) B1_A12(3.2,6.86) B4_A9(2.4,6.86)
  rect 0.3x1.14 smd mask+0.05: A5(-1.25,6.86) A6(-0.25,6.86) A7(0.25,6.86) A8(1.25,6.86) B5(1.75,6.86) B6(0.75,6.86) B7(-0.75,6.86) B8(-1.75,6.86)
  oval 1.1x2.2 hole 0.6 slot 1.7 at 90 deg mask+0.075: S1(-4.325,6.27) S2(4.325,6.27)
  oval 1.1x1.9 hole 0.6 slot 1.4 at 90 deg mask+0.075: S3(-4.325,2.09) S4(4.325,2.09)
  body extent -4.47,-0.5 4.47,7.4, height 3.22
BGA8_M040_1.24X1.75_WLCSP [mm] "BGA, 8 pin. U100"
  round 0.21 smd mask+0.05: A1(-0.35,0.4) A3(0.35,0.4) B2(0,0.2) C1(-0.35,0) C3(0.35,0) D2(0,-0.2) E1(-0.35,-0.4) E3(0.35,-0.4)
  body extent -0.63,-0.89 0.63,0.88, height 0.52
BGA120_M050_7.0X7.0_EFM32GGR [mm] "BGA, 120 Leads, Body 7.0x7.0mmx1,30mm, Pitch 0.50mm (191111)"
  round 0.2 smd mask+0.04: A1(-3,3) A2(-2.5,3) A3(-2,3) A4(-1.5,3) A5(-1,3) A6(-0.5,3) A7(0,3) A8(0.5,3) A9(1,3) A10(1.5,3) A11(2,3) A12(2.5,3) A13(3,3) B1(-3,2.5) B2(-2.5,2.5) B3(-2,2.5) B4(-1.5,2.5) B5(-1,2.5) B6(-0.5,2.5) B7(0,2.5) B8(0.5,2.5) B9(1,2.5) B10(1.5,2.5) B11(2,2.5) B12(2.5,2.5) B13(3,2.5) C1(-3,2) C2(-2.5,2) C3(-2,2) C4(-1.5,2) C5(-1,2) C6(-0.5,2) C7(0,2) C8(0.5,2) C9(1,2) C10(1.5,2) C11(2,2) C12(2.5,2) C13(3,2) D1(-3,1.5) D2(-2.5,1.5) D3(-2,1.5) D11(2,1.5) D12(2.5,1.5) D13(3,1.5) E1(-3,1) E2(-2.5,1) E3(-2,1) E11(2,1) E12(2.5,1) E13(3,1) F1(-3,0.5) F2(-2.5,0.5) F3(-2,0.5) F11(2,0.5) F12(2.5,0.5) F13(3,0.5) G1(-3,0) G2(-2.5,0) G3(-2,0) G11(2,0) G12(2.5,0) G13(3,0) H1(-3,-0.5) H2(-2.5,-0.5) H3(-2,-0.5) H11(2,-0.5) H12(2.5,-0.5) H13(3,-0.5) J1(-3,-1) J2(-2.5,-1) J3(-2,-1) J11(2,-1) J12(2.5,-1) J13(3,-1) K1(-3,-1.5) K2(-2.5,-1.5) K3(-2,-1.5) K11(2,-1.5) K12(2.5,-1.5) K13(3,-1.5) L1(-3,-2) L2(-2.5,-2) L3(-2,-2) L4(-1.5,-2) L5(-1,-2) L6(-0.5,-2) L7(0,-2) L8(0.5,-2) L9(1,-2) L10(1.5,-2) L11(2,-2) L12(2.5,-2) L13(3,-2) M1(-3,-2.5) M2(-2.5,-2.5) M3(-2,-2.5) M4(-1.5,-2.5) M5(-1,-2.5) M6(-0.5,-2.5) M7(0,-2.5) M8(0.5,-2.5) M9(1,-2.5) M10(1.5,-2.5) M11(2,-2.5) M12(2.5,-2.5) M13(3,-2.5) N1(-3,-3) N2(-2.5,-3) N3(-2,-3) N4(-1.5,-3) N5(-1,-3) N6(-0.5,-3) N7(0,-3) N8(0.5,-3) N9(1,-3) N10(1.5,-3) N11(2,-3) N12(2.5,-3) N13(3,-3)
  body extent -3.5,-3.5 3.5,3.5, height 1.3
C0201 [mm] "Capacitor, 9291, HiDens (170502)"
  rrect25% 0.36x0.32 smd paste-0.015: 1(-0.275,0) 2(0.275,0)
  Top Layer pour cut-out: -0.075,-0.2 -0.075,0.2 0.075,0.2 0.075,-0.2
  body extent -0.32,-0.13 0.32,0.13, height 0.3
C0201_L [mm] "Capacitor, Chip; 0.60 mm L X 0.30 mm W X 0.33 mm H body"
  rrect52% 0.31x0.34 smd: 1(-0.275,0) 2(0.275,0)
  body extent -0.3,-0.15 0.3,0.15, height 0.3
C0402 [mm] "Chip Capacitor, 2-Leads, Body 1.0x0.5mm, IPC High Density (190308)"
  rrect20% 0.5x0.5 smd mask+0.051: 1(-0.5,0) 2(0.5,0)
  Top Layer pour cut-out: -0.225,-0.3 -0.225,0.3 0.225,0.3 0.225,-0.3
  body extent -0.5,-0.25 0.5,0.25, height 0.6
C0603 [mm] "Capacitor, 0603, HiDens (190130)"
  rrect25% 0.8x0.85 smd: 1(-0.7,0) 2(0.7,0)
  Top Layer pour cut-out: -0.275,-0.55 -0.275,0.55 0.275,0.55 0.275,-0.55
  body extent -0.88,-0.48 0.87,0.48, height 0.95
C0805 [mm] "Capacitor, 0805 HiDens (190717)"
  rrect25% 0.95x1.35 smd: 1(-0.8,0) 2(0.8,0)
  body extent -1.1,-0.64 1.1,0.64, height 1.45
COIL_0201 [mm] "Inductor, 0201, High Density (C)"
  rrect10% 0.37x0.32 smd: 1(-0.27,0) 2(0.27,0)
  body extent -0.32,-0.17 0.32,0.17, height 0.33
COIL_0201_L [mm] "JELF243C-0021"
  rrect10% 0.3x0.3 smd: 1(-0.3,0) 2(0.3,0)
  body extent -0.32,-0.17 0.32,0.17, height 0.33
COIL_0603_L [mm] "COIL 0603_L (= L0603_0.8_L)"
  rrect10% 0.75x0.88 smd: 1(-0.725,0) 2(0.725,0)
  body extent -0.8,-0.4 0.8,0.4, height 0.8
COIL_0805_H0.9 [mm] "COIL 0805 H:0.9 (170519)"
  rrect10% 0.9x1 smd: 1(-1.05,0) 2(1.05,0)
  body extent -1,-0.6 1,0.6, height 0.9
DFN6_M100_3.0X3.0_EP_SI7021 [mm] "(191031)"
  rrect20% 0.85x0.45 smd: 1(-1.45,1) 2(-1.45,0) 3(-1.45,-1) 4(1.45,-1) 5(1.45,0) 6(1.45,1)
  rrect20% 1.6x2.5 smd: 7(0,0)
  body extent -1.5,-1.5 1.5,1.5, height 1.22
DO220AA [mm] "Diode DO220AA (DO-220AA) (= SMP) (Vishay) (170512)"
  rrect20% 2.67x2.54 smd: 1(-0.85,0)
  rrect20% 1x1.27 smd: 2(1.8,0)
  body extent -2,-1.09 2.1,1.09, height 1.15
FTSH_105_01_L_DV_K [mm]
  rrect20% 0.74x2.79 smd mask+0.051: 1(-2.54,-2.035) 2(-2.54,2.035) 3(-1.27,-2.035) 4(-1.27,2.035) 5(0,-2.035) 6(0,2.035) 7(1.27,-2.035) 8(1.27,2.035) 9(2.54,-2.035) 10(2.54,2.035)
  body extent -3.17,-2.92 3.17,2.92, height 6.13
HDR_M254-1X10_PLUS_1X10_NO_3D [mm] "No 3D model for this component"
  round 1.6 hole 1: 1(0,-25.4) 2(0,0) 3(2.54,-25.4) 4(2.54,0) 5(5.08,-25.4) 6(5.08,0) 7(7.62,-25.4) 8(7.62,0) 9(10.16,-25.4) 10(10.16,0) 11(12.7,-25.4) 12(12.7,0) 13(15.24,-25.4) 14(15.24,0) 15(17.78,-25.4) 16(17.78,0) 17(20.32,-25.4) 18(20.32,0) 19(22.86,-25.4) 20(22.86,0)
HOLE_2.2_NPL [mm] "HOLE_2.2_NPL (171218)"
  round 0 hole 2.2 unplated mask+0.1: 1(0,0)
LED_0402_CAT2 [mm] "(200921)"
  rrect10% 0.45x0.6 smd: 1(-0.45,0) 2(0.45,0)
  body extent -0.55,-0.33 0.55,0.33, height 0.25
LLP8_MA65_W3.0 [mm] "LLP8_MA65_W3.0 (180615)"
  rrect20% 0.5x0.25 smd: 1(-1.15,0.75) 2(-1.15,0.25) 3(-1.15,-0.25) 4(-1.15,-0.75) 5(1.15,-0.75) 6(1.15,-0.25) 7(1.15,0.25) 8(1.15,0.75)
  rrect20% 1.2x1.5 smd: 9(0,0)
  body extent -1.55,-1.3 1.55,1.3, height 0.8
LOGO_GECKO_H4.0_SM [mm]
LOGO_SEGGER_8.0X4.0_SM [mm] "(210607)"
LOGO_SILABS_W14.0_SILK [mm] "LOGO_SILABS_W14.0 SILKSCREEN ONLY"
  silkscreen extent 0.03,0 13.99,6.83
MIC_KNOWLES_SPK0641HT4H-1 [mm] "Microphone KNOWLES SPK0641HT4H-1 3.0x4.0x1.0 (180618)"
  rrect10% 0.45x0.95 smd mask+0.05: 1(-0.425,-0.675) 2(-0.425,0.675) 3(0.425,0.675) 4(0.425,-0.675)
  rrect10% 1.3x0.325 smd mask+0.05: 5(0,-1.725) 7(0,1.725)
  rrect10% 0.375x2.3 smd mask+0.05: 6(-1.225,0) 8(1.225,0)
  body extent -1.5,-2 1.5,2, height 1.01
POWERPAK_SC70-6 [mm] "POWERPAK SC70-6 HiDens (Vishay) (170926)"
  rrect10% 0.325x0.3 smd paste-0.025 mask+0.07: 1(-0.913,0.65) 2(-0.913,0) 3(-0.913,-0.65) 4(0.913,-0.65) 5(0.913,0) 6(0.913,0.65)
  rrect10% 0.95x0.613 smd paste-0.025 mask+0.07: 7(0,0.466) 8(0,-0.466)
  body extent -1.02,-1.02 1.02,1.05, height 0.8
PROTO_TH [mil] "Test Point, 1.0 mm (= TP_1.0_D62)"
  round 62 hole 39.37: 1(0,0)
QFN14_M040_2.0X2.0_TI_RUC [mm] "QFN 14 Leads, Pitch 0.4 mm, 2.0 x 2.0 H: 0.37, TI: RUC (180613)"
  rrect20% 0.68x0.2 smd: 1(-0.885,0.8) 2(-0.885,0.4) 3(-0.885,0) 4(-0.885,-0.4) 5(-0.885,-0.8) 8(0.885,-0.8) 9(0.885,-0.4) 10(0.885,0) 11(0.885,0.4) 12(0.885,0.8)
  rrect20% 0.2x0.68 smd: 6(-0.2,-0.885) 7(0.2,-0.885) 13(0.2,0.885) 14(-0.2,0.885)
  body extent -1,-1 1,1, height 0.41
QFN24_M050_4.0X4.0_NO_EP_ICM-20689 [mm] "QFN24, Pitch 0.50 4.0x4.0 H0.8 (210611)"
  rrect20% 0.25x0.25 smd: 1(-1.875,1.25) 6(-1.875,-1.25) 7(-1.25,-1.875) 12(1.25,-1.875) 13(1.875,-1.25) 18(1.875,1.25) 19(1.25,1.875) 24(-1.25,1.875)
  rrect20% 0.35x0.25 smd: 2(-1.825,0.75) 3(-1.825,0.25) 4(-1.825,-0.25) 5(-1.825,-0.75) 14(1.825,-0.75) 15(1.825,-0.25) 16(1.825,0.25) 17(1.825,0.75)
  rrect20% 0.25x0.35 smd: 8(-0.75,-1.825) 9(-0.25,-1.825) 10(0.25,-1.825) 11(0.75,-1.825) 20(0.75,1.825) 21(0.25,1.825) 22(-0.25,1.825) 23(-0.75,1.825)
  Top Layer region: 1.9,-1.125 1.9,-1.375 1.76,-1.375 1.758,-1.375 1.753,-1.374 1.749,-1.372 1.744,-1.369 1.743,-1.368 1.743,-1.368 1.657,-1.282 1.656,-1.281 1.653,-1.276 1.651,-1.272 1.65,-1.267 1.65,-1.265 1.65,-1.265 1.65,-1.15 1.65,-1.148 1.651,-1.143 1.653,-1.138 1.656,-1.134 1.659,-1.131 1.663,-1.128 1.668,-1.126 1.673,-1.125 1.675,-1.125 1.675,-1.125
  Top Layer region: -1.9,-1.125 -1.9,-1.375 -1.76,-1.375 -1.758,-1.375 -1.753,-1.374 -1.749,-1.372 -1.744,-1.369 -1.743,-1.368 -1.743,-1.368 -1.657,-1.282 -1.656,-1.281 -1.653,-1.276 -1.651,-1.272 -1.65,-1.267 -1.65,-1.265 -1.65,-1.265 -1.65,-1.15 -1.65,-1.148 -1.651,-1.143 -1.653,-1.138 -1.656,-1.134 -1.659,-1.131 -1.663,-1.128 -1.668,-1.126 -1.673,-1.125 -1.675,-1.125 -1.675,-1.125
  Top Layer region: -1.125,-1.9 -1.375,-1.9 -1.375,-1.76 -1.375,-1.758 -1.374,-1.753 -1.372,-1.749 -1.369,-1.744 -1.368,-1.743 -1.368,-1.743 -1.282,-1.657 -1.281,-1.656 -1.276,-1.653 -1.272,-1.651 -1.267,-1.65 -1.265,-1.65 -1.265,-1.65 -1.15,-1.65 -1.148,-1.65 -1.143,-1.651 -1.138,-1.653 -1.134,-1.656 -1.131,-1.659 -1.128,-1.663 -1.126,-1.668 -1.125,-1.673 -1.125,-1.675 -1.125,-1.675
  Top Layer region: 1.125,-1.9 1.375,-1.9 1.375,-1.76 1.375,-1.758 1.374,-1.753 1.372,-1.749 1.369,-1.744 1.368,-1.743 1.368,-1.743 1.282,-1.657 1.281,-1.656 1.276,-1.653 1.272,-1.651 1.267,-1.65 1.265,-1.65 1.265,-1.65 1.15,-1.65 1.148,-1.65 1.143,-1.651 1.138,-1.653 1.134,-1.656 1.131,-1.659 1.128,-1.663 1.126,-1.668 1.125,-1.673 1.125,-1.675 1.125,-1.675
  Top Layer region: 1.9,1.125 1.9,1.375 1.76,1.375 1.758,1.375 1.753,1.374 1.749,1.372 1.744,1.369 1.743,1.368 1.743,1.368 1.657,1.282 1.656,1.281 1.653,1.276 1.651,1.272 1.65,1.267 1.65,1.265 1.65,1.265 1.65,1.15 1.65,1.148 1.651,1.143 1.653,1.138 1.656,1.134 1.659,1.131 1.663,1.128 1.668,1.126 1.673,1.125 1.675,1.125 1.675,1.125
  Top Layer region: 1.125,1.9 1.375,1.9 1.375,1.76 1.375,1.758 1.374,1.753 1.372,1.749 1.369,1.744 1.368,1.743 1.368,1.743 1.282,1.657 1.281,1.656 1.276,1.653 1.272,1.651 1.267,1.65 1.265,1.65 1.265,1.65 1.15,1.65 1.148,1.65 1.143,1.651 1.138,1.653 1.134,1.656 1.131,1.659 1.128,1.663 1.126,1.668 1.125,1.673 1.125,1.675 1.125,1.675
  Top Layer region: -1.125,1.9 -1.375,1.9 -1.375,1.76 -1.375,1.758 -1.374,1.753 -1.372,1.749 -1.369,1.744 -1.368,1.743 -1.368,1.743 -1.282,1.657 -1.281,1.656 -1.276,1.653 -1.272,1.651 -1.267,1.65 -1.265,1.65 -1.265,1.65 -1.15,1.65 -1.148,1.65 -1.143,1.651 -1.138,1.653 -1.134,1.656 -1.131,1.659 -1.128,1.663 -1.126,1.668 -1.125,1.673 -1.125,1.675 -1.125,1.675
  Top Layer region: -1.9,1.125 -1.9,1.375 -1.76,1.375 -1.758,1.375 -1.753,1.374 -1.749,1.372 -1.744,1.369 -1.743,1.368 -1.743,1.368 -1.657,1.282 -1.656,1.281 -1.653,1.276 -1.651,1.272 -1.65,1.267 -1.65,1.265 -1.65,1.265 -1.65,1.15 -1.65,1.148 -1.651,1.143 -1.653,1.138 -1.656,1.134 -1.659,1.131 -1.663,1.128 -1.668,1.126 -1.673,1.125 -1.675,1.125 -1.675,1.125
  Top Layer pour cut-out: -2.2,2.2 -2.2,-2.2 2.2,-2.2 2.2,2.2
  body extent -2,-2 2,2, height 0.81
QFN40_M040_5.0X5.0_EP_SL [mm] "40-Pin QFP, 5.0x5.0x0.875, Pitch 0.4, EP (LT: UJ) (190909)"
  rrect2% 3.85x3.85 smd paste-2.01: 0(0,0)
  rrect25% 0.74x0.22 smd: 1(-2.495,1.8) 2(-2.495,1.4) 3(-2.495,1) 4(-2.495,0.6) 5(-2.495,0.2) 6(-2.495,-0.2) 7(-2.495,-0.6) 8(-2.495,-1) 9(-2.495,-1.4) 10(-2.495,-1.8) 21(2.495,-1.8) 22(2.495,-1.4) 23(2.495,-1) 24(2.495,-0.6) 25(2.495,-0.2) 26(2.495,0.2) 27(2.495,0.6) 28(2.495,1) 29(2.495,1.4) 30(2.495,1.8)
  rrect25% 0.22x0.74 smd: 11(-1.8,-2.495) 12(-1.4,-2.495) 13(-1,-2.495) 14(-0.6,-2.495) 15(-0.2,-2.495) 16(0.2,-2.495) 17(0.6,-2.495) 18(1,-2.495) 19(1.4,-2.495) 20(1.8,-2.495) 31(1.8,2.495) 32(1.4,2.495) 33(1,2.495) 34(0.6,2.495) 35(0.2,2.495) 36(-0.2,2.495) 37(-0.6,2.495) 38(-1,2.495) 39(-1.4,2.495) 40(-1.8,2.495)
  body extent -2.5,-2.5 2.5,2.5, height 0.86
R0201 [mm] "Resistor (Chip2PinSM127P600-8N) (170921)"
  rrect25% 0.34x0.32 smd: 1(-0.3,0) 2(0.3,0)
  Top Layer pour cut-out: -0.1,-0.2 -0.1,0.2 0.1,0.2 0.1,-0.2
  body extent -0.32,-0.13 0.32,0.13, height 0.3
R0402 [mm] "Chip Resistor, 2-Leads, Body 1.0x0.5mm, HiDens (190308)"
  rrect20% 0.6x0.6 smd mask+0.051: 1(-0.45,0) 2(0.45,0)
  Top Layer pour cut-out: -0.125,-0.3 -0.125,0.3 0.125,0.3 0.125,-0.3
  body extent -0.5,-0.25 0.5,0.25, height 0.6
SENS_VISH_VEML6035 [mm] "(200529)"
  rrect25% 0.65x0.5 smd: 1(-0.825,0.65) 2(-0.825,0) 3(-0.825,-0.65) 4(0.825,-0.65) 5(0.825,0) 6(0.825,0.65)
  body extent -1,-1 1,1, height 0.41
SOT23-5 [mm] "SOT23, 5-Leads, Body 2.95x2.8, Pitch 0.95, HiDens (170509)"
  rrect50% 0.9x0.6 smd paste-0.04 mask+0.05: 1(-1.2,0.95) 2(-1.2,0) 3(-1.2,-0.95) 4(1.2,-0.95) 5(1.2,0.95)
  body extent -1.25,-1.5 1.25,1.5, height 1.11
SOT563 [mm] "SOT563 (_M050_W1.2_), 6-Leads, Body 1.60x1.20, Pitch 0.5, HiDens (170926)"
  rrect25% 0.6x0.3 smd: 1(-0.65,0.5) 2(-0.65,0) 3(-0.65,-0.5) 4(0.65,-0.5) 5(0.65,0) 6(0.65,0.5)
  body extent -0.65,-0.85 0.65,0.85, height 0.6
SOT563_DIODES [mm] "SOT563 (_M050_W1.2_), 6-Leads, Body 1.60x1.20, Pitch 0.5, HiDens (170926)"
  rrect25% 0.5x0.375 smd: 1(-0.85,0.5) 2(-0.85,0) 3(-0.85,-0.5) 4(0.85,-0.5) 5(0.85,0) 6(0.85,0.5)
  body extent -0.66,-0.85 0.65,0.85, height 0.6
SOT663_NXP [mm] "(201120)"
  rrect25% 0.55x0.55 smd paste-0.025: 1(-0.825,0.5) 2(-0.825,-0.5) 3(0.825,0)
  body extent -0.65,-0.85 0.65,0.85, height 0.6
SOTFL50P160X60-5L [mm] "SOTFL, 5-Leads, Body 1.60x1.60mm, Pitch 0.50mm, IPC High Density"
  rect 0.4x0.25 smd: 1(-0.75,0.5) 2(-0.75,0) 3(-0.75,-0.5) 4(0.75,-0.5) 5(0.75,0.5)
  body extent -0.63,-0.83 0.63,0.82, height 0.6
SW_CK_PTS810_SJM_250 [mm] "Switch C&K PTS810_SJM_250 (grey button) (180319)"
  rrect20% 1.05x0.65 smd: 1(-2.075,1.075) 2(2.075,1.075) 3(-2.075,-1.075) 4(2.075,-1.075)
  body extent -2.29,-1.6 2.29,1.6, height 2.5
TDFN8_M050_2.0X3.0_EP [mm] "TDFN8_M050_2.0x3.0_EP (170921)"
  rrect20% 0.75x0.3 smd: 1(-1.45,0.75) 2(-1.45,0.25) 3(-1.45,-0.25) 4(-1.45,-0.75) 5(1.45,-0.75) 6(1.45,-0.25) 7(1.45,0.25) 8(1.45,0.75)
  rrect10% 1.5x1.4 smd: 9(0,0)
  body extent -1.5,-1 1.5,1, height 1.01
TP_1.0_SMD [mm] "Test Point, 1.0 mm, SMD (170509)"
  round 1 smd paste-0.501: 1(0,0)
  body extent -0.5,-0.5 0.5,0.5, height 0.04
X_KDS_DST1610A_1610 [mm] "Crystal KDS DST1610A (2 pin) (190827)"
  rrect25% 0.4x0.8 smd mask+0.051: 1(-0.5,0) 2(0.5,0)
  body extent -0.8,-0.5 0.8,0.5, height 0.45
X_KDS_DSX211SH_2.0X1.65-4 [mm] "X_KDS_DSX211SH_2.0X1.65-4 (190312)"
  rrect20% 0.9x0.8 smd: 1(-0.7,-0.55) 2(0.7,-0.55) 3(0.7,0.55) 4(-0.7,0.55)
  body extent -1.07,-0.87 1.07,0.87, height 0.5
X_TAI-SAW_TZ3398B-4 [mm] "Crystal, Tai-Saw, 4 Leads,  2.05x1.65x0.4 (190827)"
  rrect20% 0.95x0.85 smd mask+0.051: 1(-0.725,-0.575) 2(0.725,-0.575) 3(0.725,0.575) 4(-0.725,0.575)
  body extent -1.07,-0.87 1.07,0.87, height 0.51

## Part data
C29 C32: library part 150P
LED900: library part Blue

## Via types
v1: diameter 0.508, hole 0.25, Top Layer to Bottom Layer, tented both sides, 475 vias
v2: diameter 0.5, hole 0.25, Top Layer to Bottom Layer, tented both sides, 12 vias

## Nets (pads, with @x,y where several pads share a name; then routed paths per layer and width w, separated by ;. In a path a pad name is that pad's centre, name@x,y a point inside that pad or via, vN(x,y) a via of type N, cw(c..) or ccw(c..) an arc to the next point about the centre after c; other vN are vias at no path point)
3V3: C917.1 EXP1.20 Q901.1 Q902.4 R908.2 R918.2 U902.1 U902.4 | length 65
  Signal Layer 5 w0.508: v1(7.25,40.4) 7.55,40.4 ; 7.95,39.25 7.95,39.05 ; EXP1.20@27.886,12.5 25.45,14.936 25.45,15.625 25.087,15.988 18.087,15.988 15.035,19.04 15.035,20.65 14.685,21 13.871,21 13.297,21.575 12.775,21.575 11.675,22.675 11.675,27.075 10.339,28.411 10.339,30.011 9.375,30.975 9.335,30.975 9.335,35.203 8.978,35.56 8.235,35.56 ; 7.55,40.4 v1(7.95,40.4) 7.95,40 ; 7.55,40.4 7.95,40 ; 7.625,35.56 v1(7.93,35.255) 8.235,35.56 ; 7.625,35.56 7.4,35.785 7.4,38.5 7.95,39.05 ; 7.625,35.56 8.235,35.56 ; 7.95,39.05 7.95,40
  Signal Layer 6 w0.635: v1(2.775,38.175) v1(3.4,38.175) 3.677,38.175 4.24,38.739 v1(4.24,40.081) 4.543,40.383 v1(4.804,40.383) ; v1@4.85,40.375 5.475,41 6.65,41 v1(7.25,40.4) v1(7.95,40.4) ; EXP1.20@27.836,12.45 EXP1.20@27.886,12.5
  Bottom Layer w0.102: R908.2@4.775,42.7 4.775,42.69 R908.2@4.884,42.581 ; U902.4@5.601,41.199 5.675,41.125 U902.4@5.675,41
  Bottom Layer w0.2: R908.2@4.775,42.69 4.775,41.475 5.25,41 5.475,41
  Bottom Layer w0.3: v1@3.32,38.175 3.37,38.225 R918.2@4.5,38.225 ; v1(7.93,35.255) 7.97,35.295 7.97,35.42 8.3,35.75 Q901.1@8.3,35.762
  Bottom Layer w0.305: Q902.4@4.45,37.375 Q902.4@4.45,37.398 ; 3.952,37.523 4.075,37.4 4.448,37.4 Q902.4@4.45,37.398 ; 3.952,37.523 3.9,37.575 4.25,37.575 Q902.4@4.302,37.523 ; 3.952,37.523 Q902.4@4.302,37.523 ; Q902.4@4.302,37.523 4.448,37.523 4.45,37.52 Q902.4@4.45,37.398
  Bottom Layer w0.381: v1(4.804,40.383) 4.842,40.383 4.85,40.375 v1@4.874,40.399 ; U902.1@7.175,41 7.175,40.475 v1(7.25,40.4)
  Bottom Layer w0.5: v1(2.775,38.175) v1@3.32,38.175
  Bottom Layer w0.508: v1(4.24,40.081) 4.535,40.375 4.795,40.375 v1(4.804,40.383) ; v1@4.874,40.399 5.475,41 U902.4@5.629,41
  Bottom Layer w0.635: v1@2.775,38.163 v1@3.4,38.163 ; v1(3.4,38.175) v1@3.4,38.163 ; v1@7.285,40.475 7.36,40.4 v1(7.95,40.4) 7.95,40.475 C917.1@8.475,41 ; v1@3.4,38.163 3.812,38.163 3.9,38.075 3.9,37.575 3.4,38.075 v1@3.4,38.163
5V: C915.1 C916.1 D901.1 EXP1.18 R907.2 R938.2 U902.2 | length 60.3
  Top Layer w0.305: v1(6.526,37.176) 6.581,37.176 6.631,37.125 6.841,37.125 7.019,36.946 R938.2@7.019,36.562
  Signal Layer 3 w0.305: v1(6.526,37.176) 6.549,37.176 v1@6.554,37.171
  Signal Layer 4 w0.203: v1(7.277,39.604) 7.223,39.604 6.559,40.268 6.559,42.584 v1(8.025,44.05)
  Signal Layer 5 w0.305: 4.962,37.238 5.024,37.176 5.386,37.176 ; 5.142,37.419 5.386,37.176 ; v1(6.526,37.176) 5.386,37.176
  Signal Layer 5 w0.635: v1(7.277,39.604) 7.079,39.406 5.675,39.406 4.962,38.693 4.962,37.238 4.599,36.876 4.599,35.909 4.272,35.582 4.272,34.614 4.8,34.086 4.8,31.825 3.718,30.743 3.718,26.805 3.643,26.731 3.643,25.767 3.746,25.664 3.746,24.229 5.741,22.234 5.741,20.453 v1(8.994,17.2)
  Signal Layer 6 w0.635: v1(8.994,17.2) 10.23,15.964 26.962,15.964 EXP1.18@27.886,15.04
  Bottom Layer w0.203: R907.2@7.5,44.05 v1@8,44.05
  Bottom Layer w0.381: C915.1@6.396,39.496 6.675,39.775 C916.1@6.675,40.25 U902.2@6.675,41
  Bottom Layer w0.635: C915.1@6.475,39.55 7.223,39.55 v1(7.277,39.604) ; D901.1@8.925,19 8.994,18.931 v1(8.994,17.2)
BOARD_ID_SCL: EXP1.17 R911.1 TPJ14.1 U900.H13 U903.6 | length 56
  Signal Layer 3 w0.102: v1(24.777,15.117) 23.025,16.869 23.025,19.125 24.53,20.63 24.53,26.491 25.52,27.481 v1(25.52,30.472)
  Signal Layer 6 w0.102: EXP1.17@2.486,15.04 3.45,15.04 ; v1(9.625,22.05) 8.581,21.006 8.281,21.006 3.865,16.59 3.865,15.455 3.45,15.04 ; v1(24.777,15.117) 23.709,14.049 4.441,14.049 3.45,15.04
  Bottom Layer w0.102: v1@9.601,22.047 9.601,22.099 v1@9.625,22.123 ; v1(9.625,22.05) v1@9.625,22.123 ; v1@9.625,22.16 v1@9.625,22.123 ; U900.H13@9.731,22.481 U900.H13@9.75,22.5 9.75,22.248 v1@9.625,22.123 ; U903.6@21.226,28.649 U903.6@21.3,28.575 ; U903.6@21.525,28.55 U903.6@21.556,28.581 ; U903.6@21.562,28.587 U903.6@21.556,28.581 ; R911.1@22.419,28.575 R911.1@22.426,28.581 ; v1(25.52,30.472) 25.421,30.472 24.649,29.7 TPJ14.1@24.55,29.7 24.55,29.46 23.39,28.3 22.779,28.3 R911.1@22.467,28.612 ; U903.6@21.556,28.581 R911.1@22.426,28.581 ; R911.1@22.426,28.581 R911.1@22.457,28.612 R911.1@22.467,28.612 ; R911.1@22.426,28.581 22.436,28.581 R911.1@22.467,28.612
BOARD_ID_SDA: EXP1.19 R910.1 TPJ15.1 U900.G13 U900.H12 U900.J12 U903.5 | length 49.7
  Top Layer w0.102: v1@8.842,21.992 8.946,22.096 v1(8.998,22.096)
  Signal Layer 6 w0.102: EXP1.19@2.486,12.5 1.432,13.554 1.432,15.446 2.036,16.05 3.232,16.05 3.645,16.463 3.645,18.499 7.37,22.223 8.76,22.223 8.888,22.096 v1(8.998,22.096) ; v1@8.957,22.107 9.314,22.464 11.972,22.464 12.381,22.055 13.885,22.055 13.901,22.07 14.274,22.07 14.404,22.2 16.8,22.2 17.75,23.15 24.131,23.15 27.075,26.094 27.075,27.241 cw(c27.886,27.74) 27.062,27.263 27.045,27.279 26.875,27.45 26.875,28.4 27.325,28.85 27.325,29.325 25.558,31.092 25.185,31.092 v1(25.151,31.127)
  Bottom Layer w0.102: v1(8.998,22.096) 8.998,22.242 9.25,22.494 U900.G13@9.25,22.5 U900.H12@9.75,23 U900.J12@10.25,23 ; U903.5@21.575,29.075 22.065,29.075 22.157,29.167 R910.1@22.465,29.167 22.465,29.553 22.772,29.86 22.772,29.897 23.08,30.204 23.416,30.204 23.522,30.098 23.93,30.098 24.185,30.352 24.477,30.352 25.151,31.027 v1(25.151,31.127) 24.55,31.728 TPJ15.1@24.55,32.3
BOARD_ID_WP: R912.1 TPJ16.1 U900.F13 U903.7 | length 29.9
  Signal Layer 3 w0.102: v1(19.958,25.87) 20.902,24.926 v1(20.902,18.813)
  Signal Layer 4 w0.102: v1(8.305,21.639) 8.305,21.585 9.179,20.712 9.179,20.178 12.007,17.35 19.712,17.35 20.225,17.863 20.225,18.136 v1(20.902,18.813)
  Bottom Layer w0.102: v1(8.305,21.639) 8.305,22.055 U900.F13@8.75,22.5 ; v1(19.958,25.87) 19.958,25.92 20.171,26.132 20.171,27.182 20.431,27.443 20.868,27.443 20.998,27.573 20.998,27.748 21.3,28.05 U903.7@21.525,28.05 21.56,28.015 22.416,28.015 R912.1@22.451,27.979 ; v1(20.902,18.813) 21.887,18.813 TPJ16.1@22.45,18.25
CTRL_MCU_PA0: R919.1 U900.C2 U900.D3 | length 10.6
  Signal Layer 4 w0.102: v1(4.391,29.763) 4.666,29.488 4.903,29.25 6.165,29.25 8.925,26.49 v1@8.925,26.425 ; v1@8.925,26.367 v1@9.017,26.367
  Bottom Layer w0.102: v1(4.391,29.763) 4.41,29.743 5.943,29.743 6.182,29.982 6.182,30 R919.1@6.575,30 ; U900.C2@7.25,28 U900.D3@7.75,27.5 v1@8.806,26.444
  other v1: 8.925,26.4
CTRL_MCU_PA1: R920.1 U900.C1 | length 1.9
  Bottom Layer w0.102: R920.1@7.125,30 7.125,29.99 7.016,29.881 6.978,29.881 6.785,29.688 6.785,28.965 U900.C1@7.25,28.5
CTRL_MCU_PB10: R905.1 U900.L9 | length 33.6
  Top Layer w0.2: R905.1@21.95,3.075 22.684,3.809 22.684,14.932 v1(22.325,15.291)
  Signal Layer 5 w0.102: 9.1,24.05 9.124,24.05 9.624,24.55 v1(9.7,24.55)
  Signal Layer 5 w0.2: 9.1,24.05 9.094,24.044 9.094,23.284 12.678,19.7 13.295,19.7 13.875,19.12 13.875,18.225 17.433,14.667 21.701,14.667 v1(22.325,15.291)
  Bottom Layer w0.102: v1(9.7,24.55) 9.75,24.5 10.325,24.5 10.558,24.733 11.017,24.733 U900.L9@11.25,24.5
CTRL_MCU_PB13: U900.N9 X900.3 | length 3.3
  Bottom Layer w0.102: U900.N9@12.25,24.5 12.514,24.236 13.336,24.236 13.55,24.45 14.5,24.45 15.1,25.05 X900.3@15.1,25.1
CTRL_MCU_PB14: U900.N10 X900.1 | length 1.9
  Bottom Layer w0.102: U900.N10@12.25,24 13.7,24 X900.1@14,23.7
CTRL_MCU_PC2: R921.1 U900.L1 | length 1.6
  Bottom Layer w0.102: U900.L1@11.25,28.5 11.25,28.939 11.292,28.981 11.292,29.091 11.775,29.574 R921.1@11.775,29.925
  other v1: 11.37,29.169
CTRL_MCU_PC14: R922.1 U900.C12 U900.C13 | length 27.3
  Signal Layer 4 w0.102: v1(2.975,16.501) 4.307,17.832 v1(7.046,17.832)
  Bottom Layer w0.102: v1(2.975,16.501) 2.899,16.425 2.075,16.425 1.475,17.025 1.475,28.65 2.125,29.3 3.2,29.3 3.776,29.876 R922.1@3.776,30.801 R922.1@3.674,30.902 ; v1(7.046,17.832) 7.107,17.832 7.333,18.058 7.333,19.327 7.253,19.407 7.253,22.497 U900.C13@7.25,22.5 U900.C12@7.25,23
CTRL_MCU_PD0: C923.1 R901.1 U900.L10 | length 5.9
  Top Layer w0.102: v1@10.742,24.326 v1@10.749,24.326
  Signal Layer 5 w0.102: v1@10.767,24.301 10.767,22.942 11.79,21.919 11.79,21.698 v1(11.865,21.623)
  Bottom Layer w0.102: v1@10.742,24.326 10.742,24.308 11.05,24 U900.L10@11.25,24 ; v1(11.865,21.623) 11.916,21.571 11.916,21.234 R901.1@11.968,21.182 11.968,20.382 12.548,19.802 C923.1@12.548,19.782
  other v1: 10.767,24.326
CTRL_MCU_PD5: R930.1 U900.N13 | length 1.5
  Bottom Layer w0.102: U900.N13@12.25,22.5 12.25,22.1 12.775,21.575 R930.1@12.775,21.185
CTRL_MCU_PE4: R931.1 U900.C11 | length 11.6
  Signal Layer 3 w0.102: v1(5.66,19.425) 5.66,22.099 8.536,24.975 9.299,24.975 v1(9.525,25.201)
  Bottom Layer w0.102: R931.1@5.025,19.45 5.037,19.438 5.647,19.438 v1(5.66,19.425) ; U900.C11@7.25,23.5 7.555,23.805 7.555,24.009 8.521,24.975 9.299,24.975 v1(9.525,25.201)
CTRL_MCU_PF5: TP999.1 U900.A8 | length 29.9
  Signal Layer 5 w0.102: TP999.1@4.65,2.5 2.775,4.375 2.775,10.116 3.959,11.3 6.298,11.3 9.463,14.465 9.463,17.637 6.284,20.816 6.284,22.766 6.284,24.767 v1(5.741,25.31)
  Bottom Layer w0.102: v1(5.741,25.31) 6.051,25 U900.A8@6.25,25
CTRL_MCU_PF7: R932.1 U900.A7 | length 1.8
  Bottom Layer w0.102: R932.1@4.97,25.201 4.97,25.211 5.241,25.483 5.241,25.681 5.385,25.825 5.98,25.825 6.25,25.555 U900.A7@6.25,25.5
CTRL_MCU_PF10: R903.2 U900.B13 | length 1.7
  Bottom Layer w0.203: U900.B13@6.75,22.5 6.548,22.298 6.548,21.252 R903.2@6.8,21
CTRL_MCU_PF11: R904.2 U900.A13 | length 1.6
  Bottom Layer w0.203: R904.2@5.92,21 6.118,21.198 6.243,21.323 6.243,22.493 U900.A13@6.25,22.5
CTRL_MCU_RESET: TPJ17.1 U900.L8 U900.M7 | length 5.7
  Signal Layer 6 w0.102: v1(10.15,25) 11.638,25 v1(12.738,26.1)
  Bottom Layer w0.102: v1(10.15,25) U900.L8@11.25,25 U900.M7@11.75,25.5 ; v1(12.738,26.1) 13.172,26.1 13.451,26.378 TPJ17.1@13.457,26.378
CTRL_MCU_RXD: TPJ6.1 U900.A1 | length 20.4
  Signal Layer 4 w0.102: v1(5.66,28.725) 6.4,28.725 8.5,26.625 8.5,26.25 8.9,25.85 9.2,25.85 9.4,25.65 10.85,25.65 11.671,25.65 12.543,24.778 12.697,24.778 v1(12.775,24.7)
  Signal Layer 5 w0.102: v1(12.775,24.7) 13.1,25.025 13.1,25.824 13.376,26.1 14.675,26.1 16.144,27.569 16.8,28.225 16.8,28.825 18.226,30.251 v1@18.226,31.102
  Bottom Layer w0.102: v1@5.55,28.725 v1(5.66,28.725) 6.025,28.725 U900.A1@6.25,28.5 ; TPJ6.1@17.22,31.57 17.29,31.5 17.827,31.5 v1@18.226,31.102
  other v1: 18.251,31.102
CTRL_MCU_SPI_CIPO: U900.A4 U900.B3 U901.C3 | length 5.8
  Top Layer w0.102: v1(2.868,26.623) 3.632,26.623 3.859,26.85 v1(5.775,26.85)
  Bottom Layer w0.102: v1(2.868,26.623) v1(2.868,26.623) 3.447,27.2 U901.C3@4.15,27.2 ; v1@5.775,26.882 v1(5.775,26.85) 5.872,26.85 6.022,27 U900.A4@6.25,27 U900.B3@6.75,27.5
CTRL_MCU_SPI_COPI: U900.C3 U901.D2 | length 19.2
  Signal Layer 6 w0.102: v1(2.075,26.326) 1.534,25.785 1.534,24.241 2.152,23.623 2.608,23.623 3.048,24.062 3.831,24.062 4.175,23.719 4.881,23.719 5,23.6 6.245,23.6 7.929,25.284 7.936,25.284 8.182,25.529 8.182,25.544 8.629,25.991 9.678,25.991 v1(9.75,26.063)
  Bottom Layer w0.102: v1(2.075,26.326) 2.59,26.326 2.764,26.152 3.548,26.152 3.775,25.925 4.458,25.925 4.756,26.224 4.756,26.525 4.521,26.76 4.521,26.979 U901.D2@4.5,27 ; U900.C3@7.25,27.5 7.642,27.108 7.799,27.108 8.48,26.428 8.48,26.27 8.79,25.96 9.473,25.96 v1@9.6,26.088
CTRL_MCU_SPI_CS: R906.1 U900.B1 U900.B2 U901.A3 | length 5.8
  Bottom Layer w0.102: U901.A3@4.15,27.6 3.75,28 3.75,28.95 3.951,29.151 R906.1@4.253,29.151 ; R906.1@4.248,28.991 4.258,28.991 4.367,29.1 R906.1@4.367,29.11 ; R906.1@4.248,29.091 4.258,29.091 4.286,29.118 4.464,29.297 4.521,29.297 4.697,29.472 5.778,29.472 U900.B1@6.75,28.5 U900.B2@6.75,28
CTRL_MCU_SPI_SCLK: U900.A3 U901.E1 | length 1.7
  Bottom Layer w0.102: U901.E1@4.85,26.8 5.55,27.5 U900.A3@6.25,27.5
CTRL_MCU_SWCLK: TPJ2.1 U900.C10 | length 31.5
  Signal Layer 5 w0.102: v1(18.765,24.909) 18.075,24.909 17.5,25.484 17.5,28.92 18.575,29.995 18.575,30.75 19.019,31.194 v1(19.025,31.194)
  Signal Layer 6 w0.102: v1(8.895,25.381) 8.6,25.087 8.6,23.886 9.603,22.883 14.078,22.883 14.117,22.844 17.147,22.844 17.75,23.447 17.75,24.204 18.377,24.831 18.687,24.831 v1(18.765,24.909)
  Bottom Layer w0.102: U900.C10@7.25,24 7.259,24 8.582,25.323 8.836,25.323 v1(8.895,25.381) ; TPJ2.1@16.3,34.38 16.775,33.905 16.775,32.335 16.616,32.176 ccw(c17.22,31.57) 16.614,32.174 16.497,32.057 15.985,31.61 15.925,31.55 15.925,31.508 15.925,30.925 16.481,30.369 18.194,30.369 19.019,31.194 v1(19.025,31.194) 18.935,31.284 18.884,31.284 v1@18.862,31.262
CTRL_MCU_SWDIO: TPJ1.1 U900.A9 U900.B10 | length 17.6
  Signal Layer 4 w0.102: v1(5.741,24.666) 5.334,24.26 5.334,23.858 5.976,23.216 11.384,23.216 12.69,23.216 13.26,22.645 13.26,22.556 13.746,22.07 13.901,22.07 14.238,22.07 14.916,21.392 14.916,19.851 14.756,19.691 v1(14.756,18.041)
  Bottom Layer w0.102: v1(5.741,24.666) 5.907,24.5 U900.A9@6.25,24.5 U900.B10@6.75,24 ; v1(14.756,18.041) 15.441,18.041 15.479,18.078 15.778,18.078 TPJ1.1@15.95,18.25
CTRL_MCU_SWO: TPJ3.1 U900.A10 | length 13.7
  Signal Layer 4 w0.102: v1(5.741,24.026) 6.317,23.45 13.775,23.45 16.446,20.779 16.482,20.779 16.595,20.667 v1(16.705,20.667)
  Bottom Layer w0.102: v1@5.751,24 U900.A10@6.25,24 ; TPJ3.1@15.9,20.8 15.967,20.733 16.638,20.733 v1(16.705,20.667)
CTRL_MCU_TEST_MODE: TPJ11.1 U900.G11 | length 20
  Signal Layer 6 w0.102: v1(9.025,24.526) 9.025,23.8 9.733,23.092 14.157,23.092 14.201,23.048 17.063,23.048 17.525,23.509 17.525,24.5 18.15,25.125 18.406,25.125 18.681,25.4 21.056,25.4 22.155,24.301 22.721,24.301 v1(22.729,24.309)
  Bottom Layer w0.102: v1(9.025,24.526) 9.025,23.725 U900.G11@9.25,23.5 U900.G11@9.206,23.5 ; v1(22.729,24.309) 22.759,24.28 24.77,24.28 TPJ11.1@24.8,24.25
CTRL_MCU_TXD: TPJ5.1 U900.A2 | length 14.5
  Signal Layer 6 w0.102: v1(5.66,28.081) 5.898,28.32 15.153,28.32 15.876,29.043 16.168,29.043 v1(16.245,29.121)
  Bottom Layer w0.102: v1(5.66,28.081) 5.741,28 U900.A2@6.25,28 ; TPJ5.1@13.75,29.2 14.225,28.725 15.549,28.725 15.867,29.043 16.168,29.043 v1(16.245,29.121)
CTRL_MCU_USB_DM: D600.4 P900.A7 P900.B7 R903.1 TPJ19.1 | length 27.5
  Top Layer w0.203: v1(7.822,15.402) 7.88,15.344 7.88,15.095 8.025,14.95 8.025,12.925 9.352,11.598 14.483,11.598 14.845,11.235 14.845,10.908 14.488,10.55 D600.4@14.212,10.275 ; D600.4@14.15,10.275 14.236,10.189 14.436,10.189 14.85,9.775 14.85,8.486 ; P900.B7@14.25,7.36 14.25,8.131 14.369,8.25 14.614,8.25 14.85,8.486 ; P900.A7@15.25,7.36 15.241,7.369 15.241,8.095 14.85,8.486
  Bottom Layer w0.203: TPJ19.1@4.2,17.9 6.271,17.9 7.912,16.259 8.291,16.259 8.45,16.1 8.45,15.8 8.325,15.675 8.012,15.675 7.822,15.485 v1(7.822,15.402) ; TPJ19.1@4.2,17.9 4.625,18.324 5.826,18.324 5.959,18.191 6.652,18.191 7.079,18.618 7.079,19.222 6.642,19.659 6.642,19.942 R903.1@6.8,20.1
CTRL_MCU_USB_DP: D600.3 P900.A6 P900.B6 R904.1 TPJ18.1 | length 28.8
  Top Layer w0.203: v1(7.416,16.07) 7.474,16.012 7.859,16.012 8.33,15.541 8.33,13.051 9.478,11.903 14.609,11.903 15.15,11.362 15.15,10.928 15.702,10.376 15.702,10.361 15.788,10.275 D600.3@15.85,10.275 15.764,10.189 15.539,10.189 15.155,9.805 15.155,8.613 15.702,8.066 15.702,7.408 P900.B6@15.75,7.36 15.75,6.573 15.631,6.454 14.896,6.454 14.75,6.6 P900.A6@14.75,7.36
  Bottom Layer w0.203: R904.1@6,20.1 6.271,19.829 6.271,18.999 TPJ18.1@6.35,18.92 6.271,18.92 6.134,18.92 5.843,18.629 3.898,18.629 3.5,18.23 3.5,18.194 3.497,18.191 3.497,17.609 3.909,17.197 4.522,17.197 4.819,17.494 6.246,17.494 6.819,16.921 7.357,16.383 7.357,16.128 v1(7.416,16.07)
DBG_3V3: C914.1 C919.1 Q902.3 Q903.4 R906.2 R910.2 R911.2 R912.2 R933.1 R936.2 U901.A1 U901.E3 U903.8 | length 48.5
  Top Layer w0.254: 5,32.025 Q903.4@5,32.55
  Top Layer w0.305: v1(4.391,30.407) 4.391,30.462 4.538,30.61 4.538,31.21 4.545,31.218 4.565,31.218 4.573,31.225 4.573,31.598 5,32.025
  Signal Layer 3 w0.203: v1(23.248,29.798) 23.248,27.91 23.425,27.733 v1(23.425,27.65)
  Signal Layer 3 w0.508: v1(2.35,34.2) v1(2.975,34.2) 4.859,32.316 4.859,30.876 ; v1(5.01,28.18) 5.01,30.005 4.859,30.156 ; 4.859,30.156 4.859,30.876 ; 4.859,30.156 4.608,30.407 v1(4.391,30.407) 4.859,30.876
  Signal Layer 6 w0.508: v1(4.316,26.358) 4.316,26.534 5.253,27.472 ; v1(5.01,28.18) 5.01,27.715 5.253,27.472 ; v1(23.425,27.65) 21.55,27.65 v1(19.7,29.5) 18.035,29.5 16.295,27.76 13.575,27.76 13.421,27.913 6.538,27.913 6.097,27.472 5.253,27.472
  Bottom Layer w0.203: U901.E3@4.15,26.8 4.151,26.799 4.151,26.605 4.316,26.44 v1(4.316,26.358) ; C914.1@4.817,28.571 4.833,28.586 4.833,29.075 R906.2@4.848,29.091 ; C914.1@4.837,28.571 4.896,28.512 4.896,28.377 5.01,28.262 5.01,28.097 4.851,27.938 U901.A1@4.85,27.6 U901.A1@4.85,27.6 ; U903.8@21.525,27.55 22.228,27.55 22.403,27.375 23.067,27.375 23.342,27.65 v1(23.425,27.65) ; R912.2@23.051,27.979 23.061,27.979 v1@23.39,27.65 ; R911.2@23.057,28.612 23.061,28.617 23.061,29.163 R910.2@23.065,29.167 23.065,29.538 23.248,29.721 v1(23.248,29.798)
  Bottom Layer w0.254: v1(2.35,34.2) v1(2.975,34.2) 2.982,34.207 3.358,34.207 3.625,34.475 3.625,35.5 4.096,35.971 4.427,35.971 4.45,35.994 Q902.3@4.45,36.075
  Bottom Layer w0.305: Q902.3@4.45,36.075 4.45,36.421 4.85,36.821 5.683,36.821 5.874,37.011 5.874,37.346 6.166,37.638 6.176,37.638 R933.1@6.176,37.648 ; C919.1@19.125,29.775 19.425,29.775 v1(19.7,29.5)
DBG_PTI_DATA: P1.10 U1.5 U900.N1 | length 29.6
  Top Layer w0.102: U1.5@14.37,33.75 14.842,33.75 15.065,33.528 v1(15.084,33.528) ; P1.10@21.015,24.94 21.05,24.975 22.19,24.975 22.383,25.169 v1(22.437,25.169)
  Signal Layer 3 w0.102: v1(22.437,25.169) 22.544,25.169 22.9,25.525 22.9,26.6 22.638,26.862 22.638,31.178 22.309,31.507 22.309,33.278 22.754,33.723 23.873,33.723 24.225,34.075 v1(24.35,34.075)
  Signal Layer 6 w0.102: v1(15.084,33.528) 15.084,33.624 15.546,34.086 19.636,34.086 19.648,34.098 20.13,34.098 20.232,34.2 22.975,34.2 23.332,34.557 23.868,34.557 v1(24.35,34.075)
  Bottom Layer w0.102: U900.N1@12.25,28.5 12.45,28.5 12.85,28.9 12.85,31.075 14.125,32.35 14.125,32.581 15.072,33.528 v1(15.084,33.528)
